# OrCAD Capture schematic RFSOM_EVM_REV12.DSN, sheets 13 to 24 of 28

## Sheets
13 09 RF_TX03: size A4
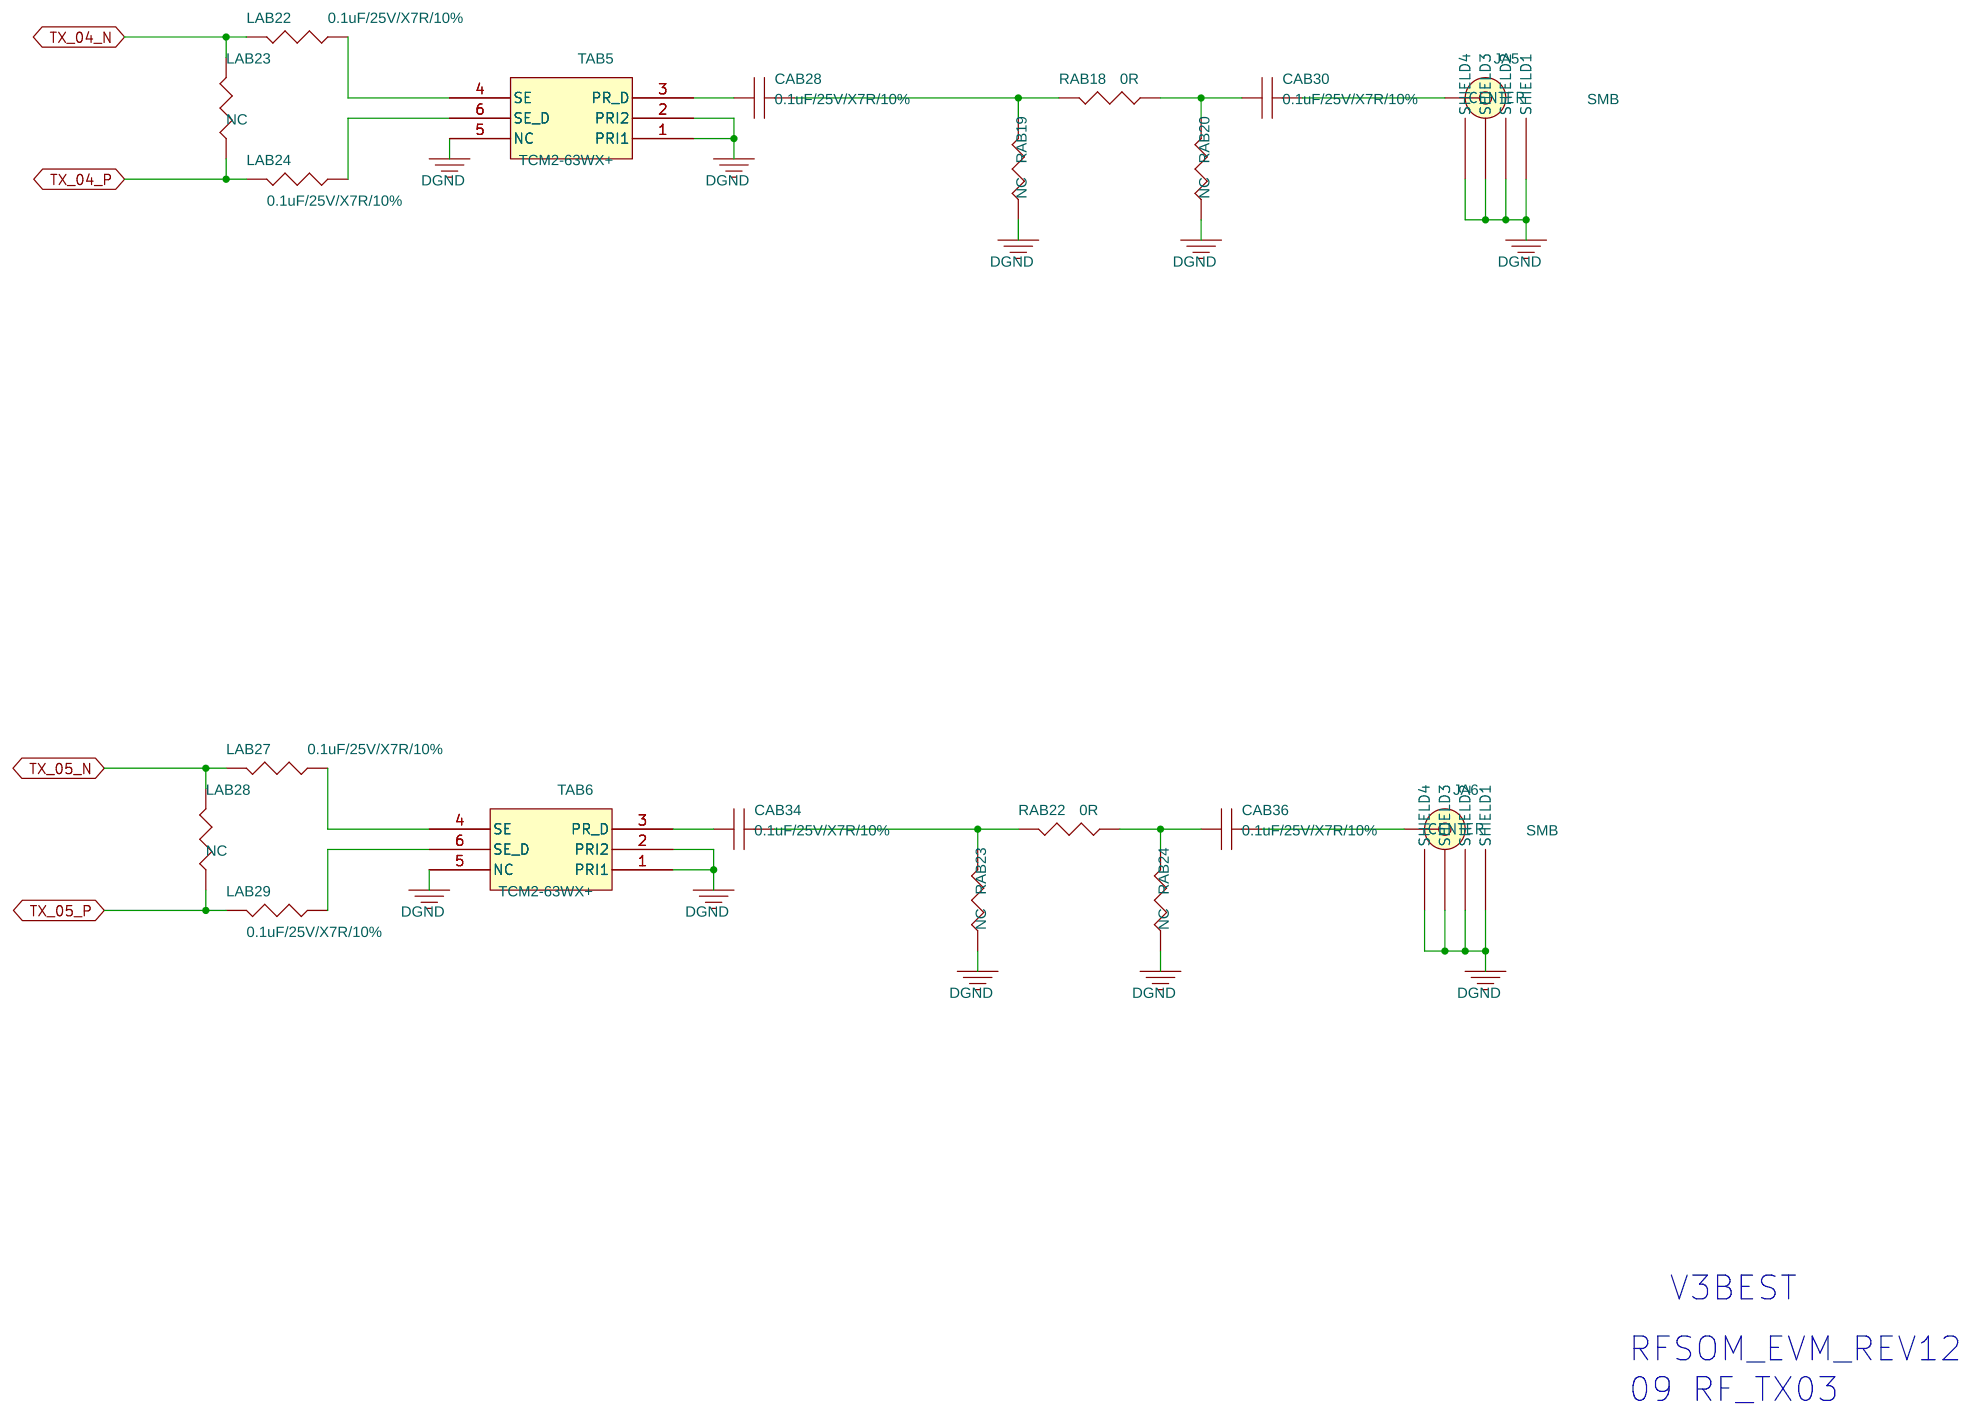
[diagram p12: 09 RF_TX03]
14 08 RF_TX02: size A4
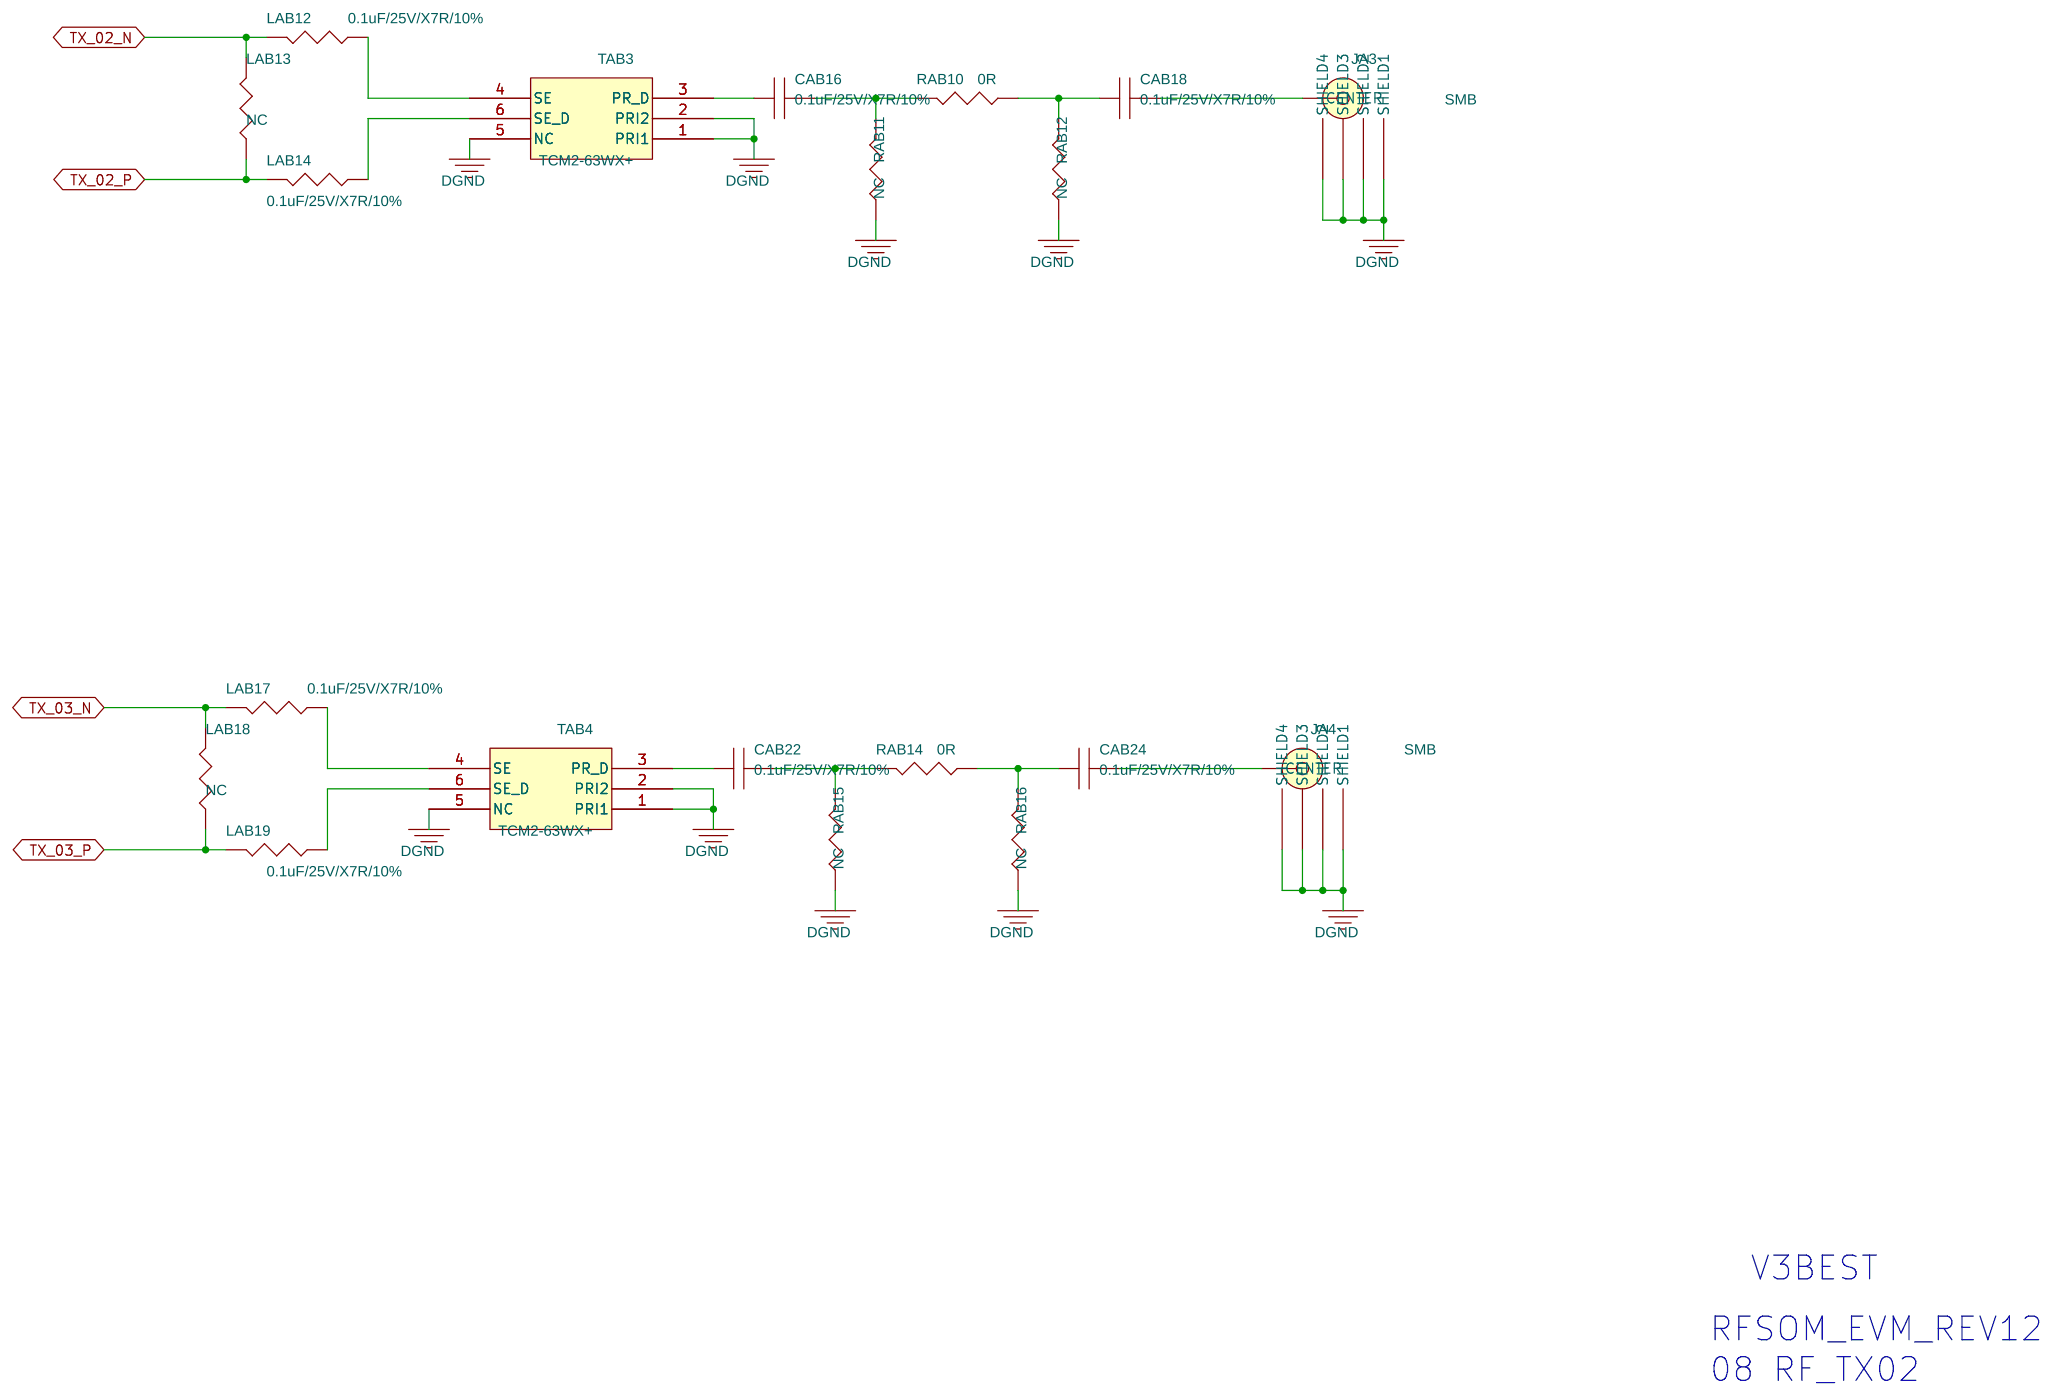
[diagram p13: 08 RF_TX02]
15 07 RF_TX01: size A4
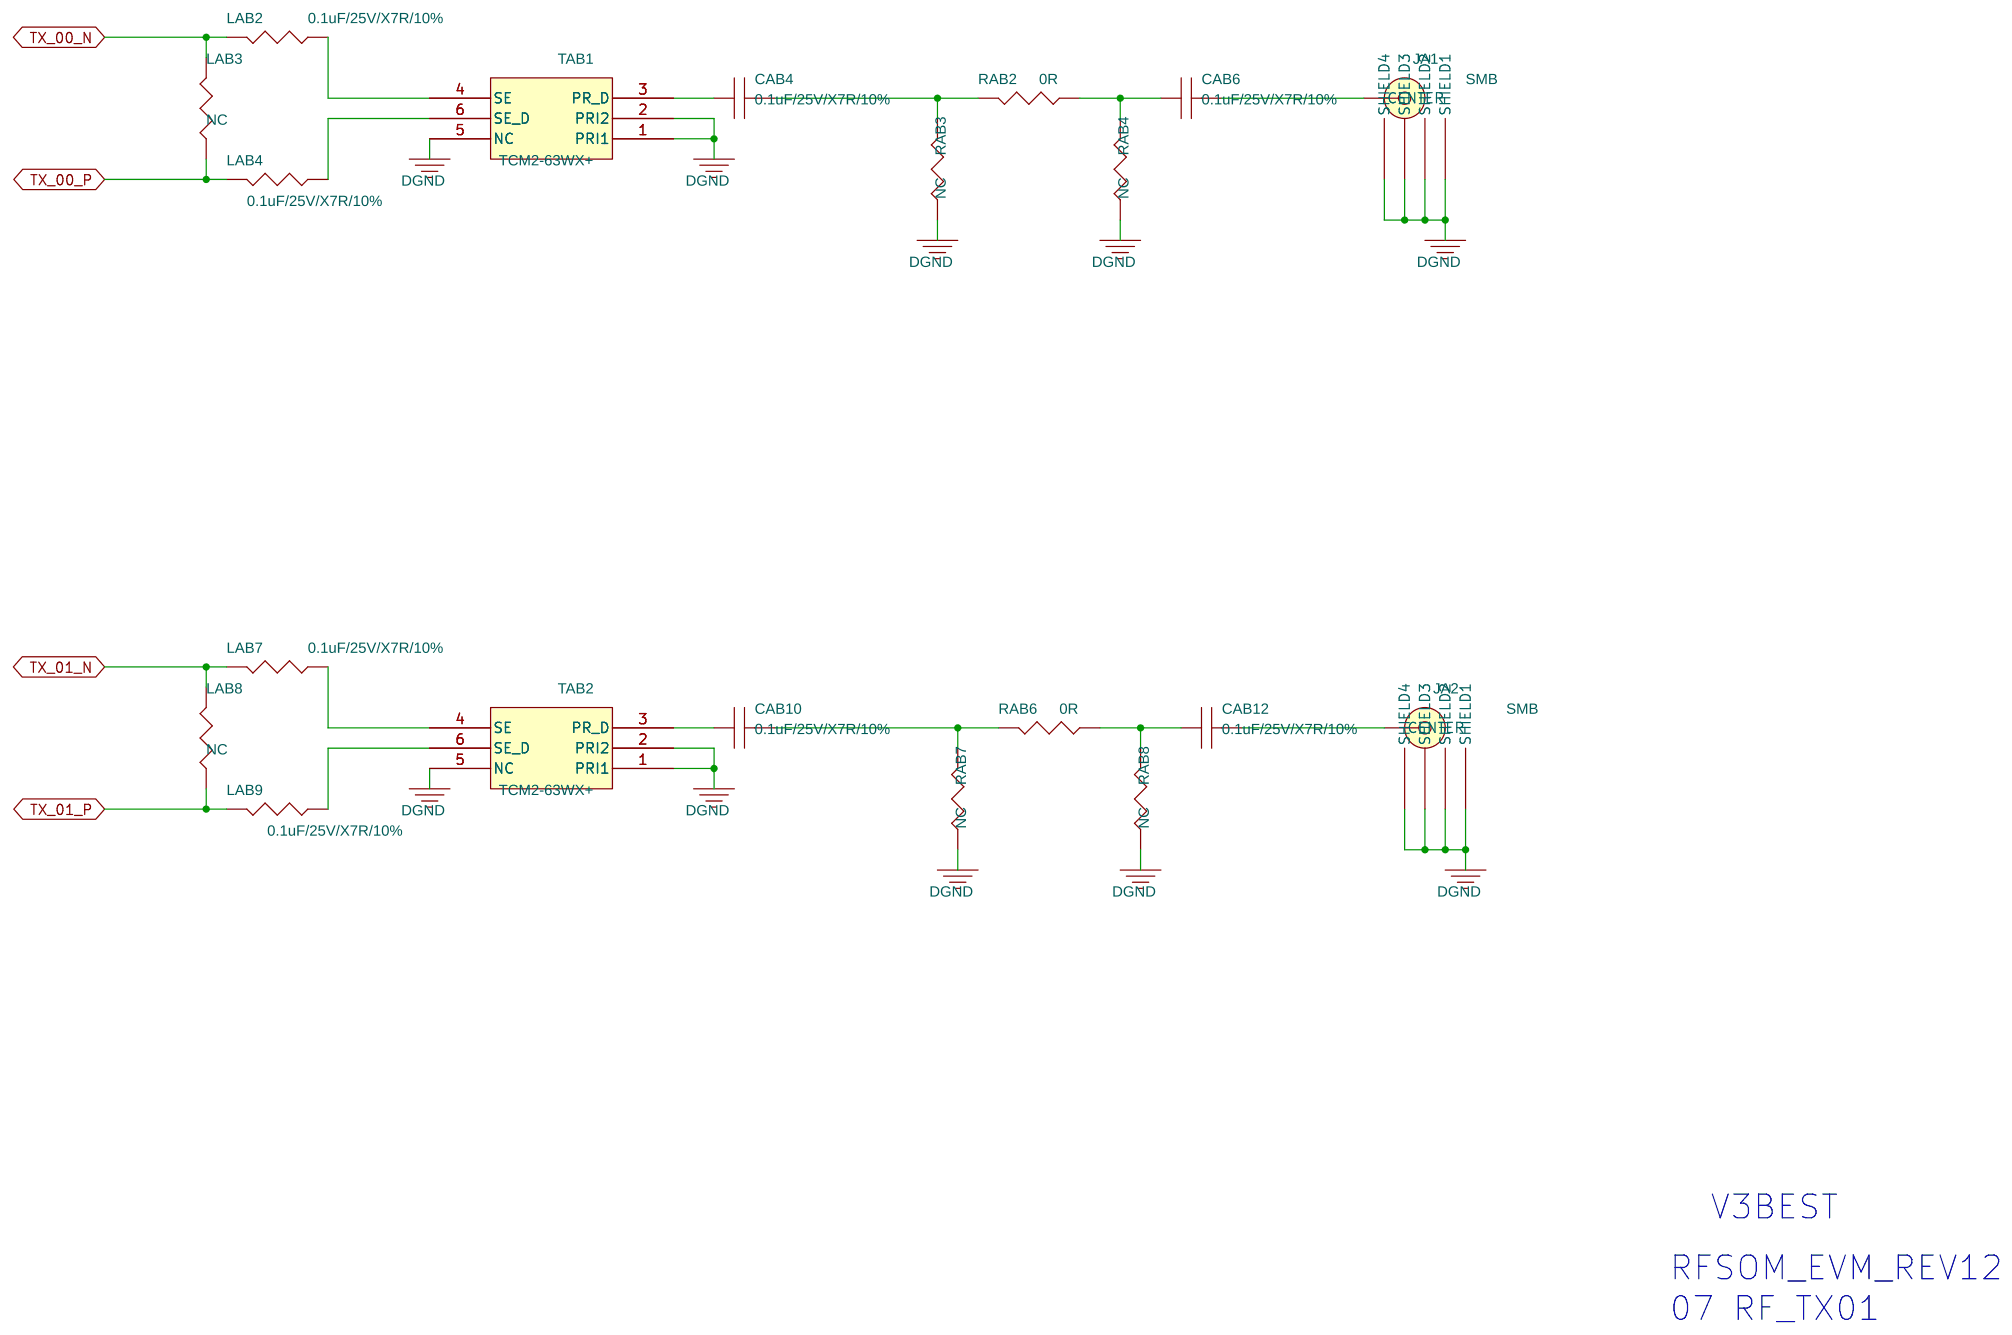
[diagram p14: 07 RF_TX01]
16 06 CORE_CONNECTOR03: size A4
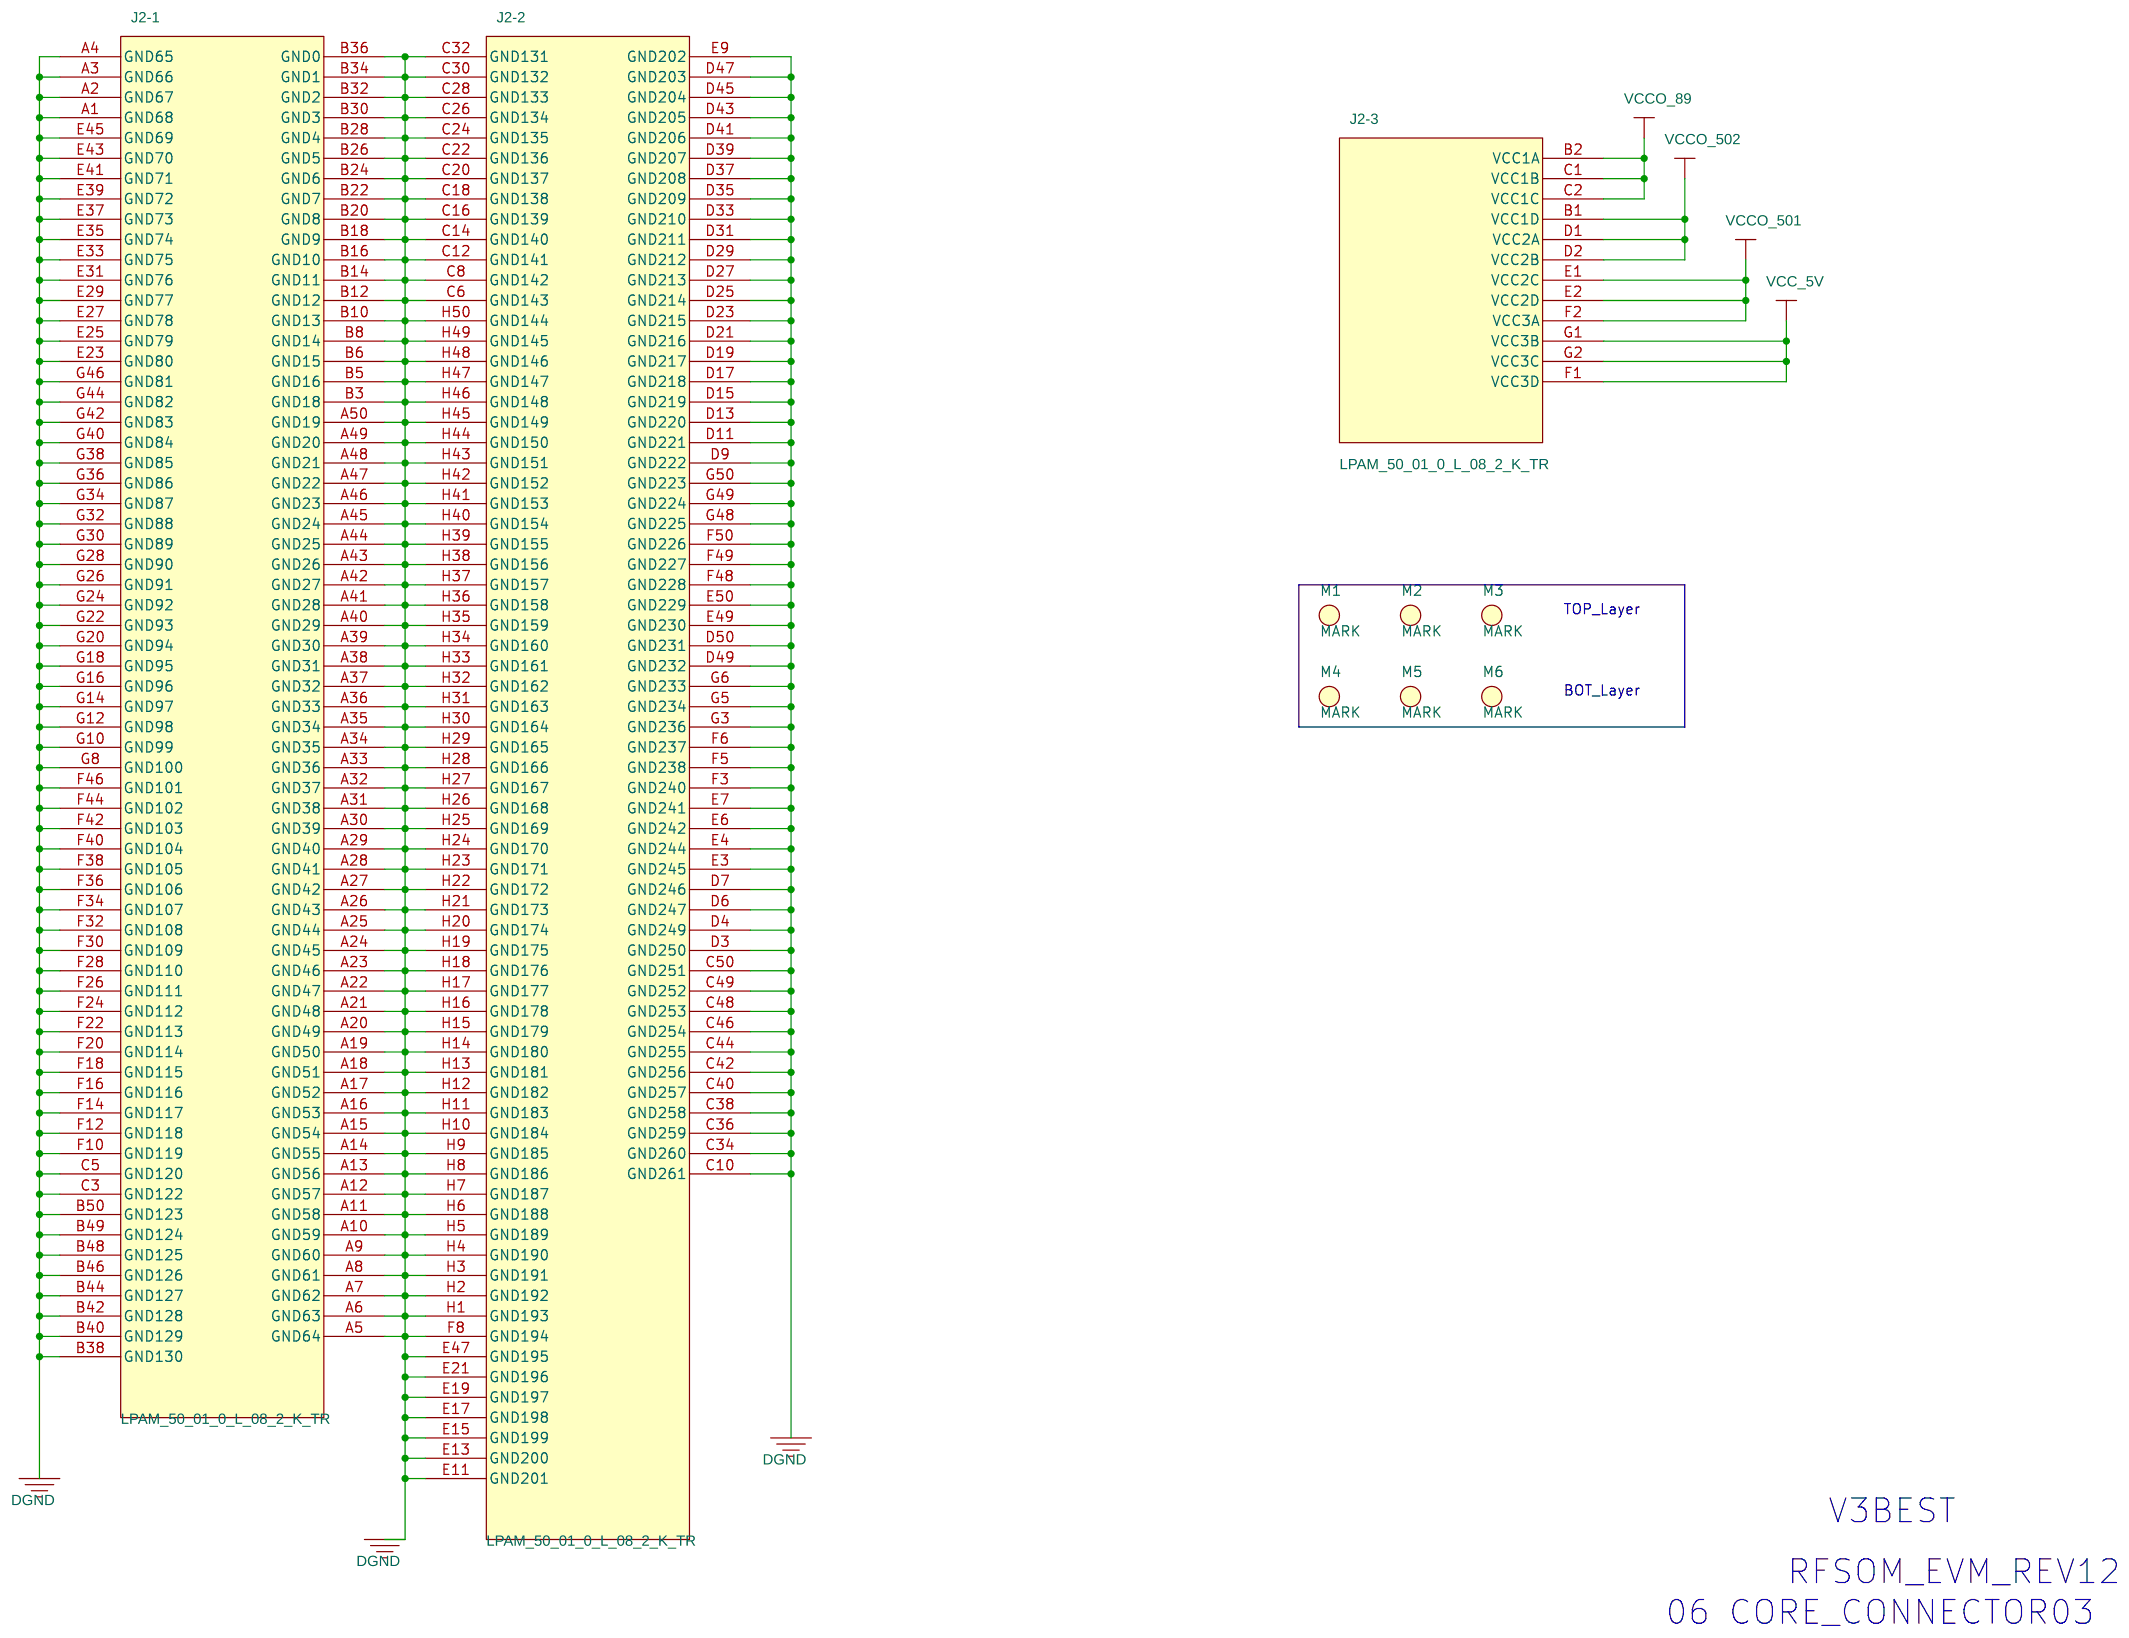
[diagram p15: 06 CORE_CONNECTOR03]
17 05 CORE_CONNECTOR02: size A4
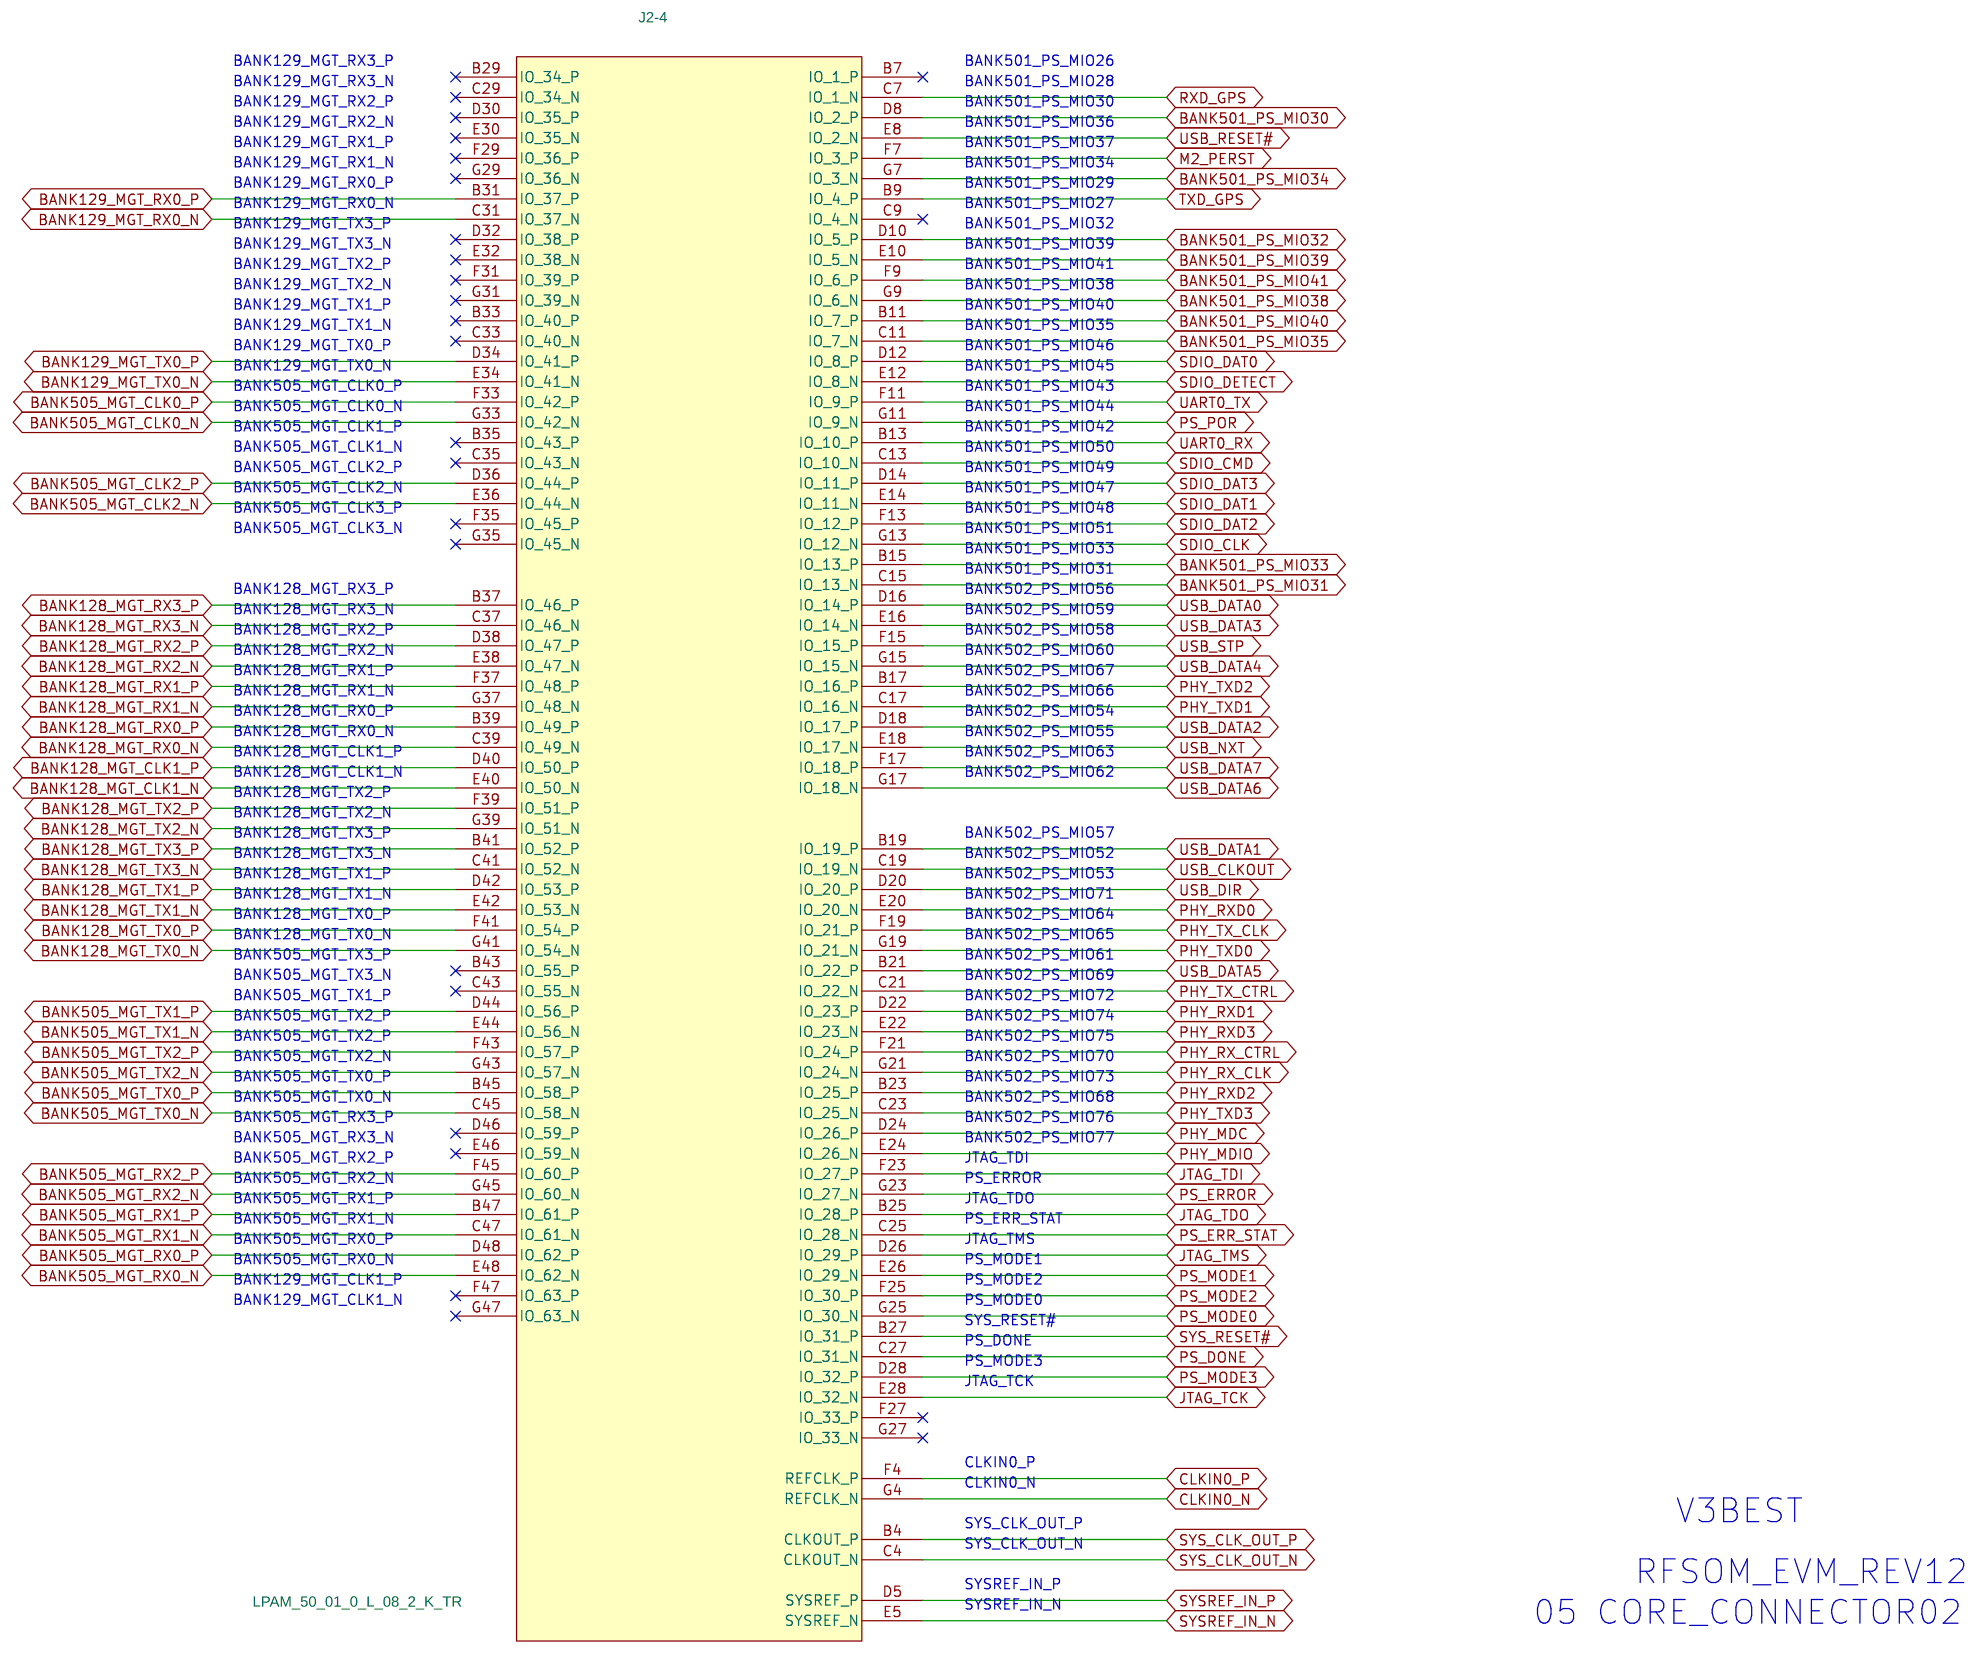
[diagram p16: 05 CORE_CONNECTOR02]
18 04 CORE_CONNECTOR01: size A4
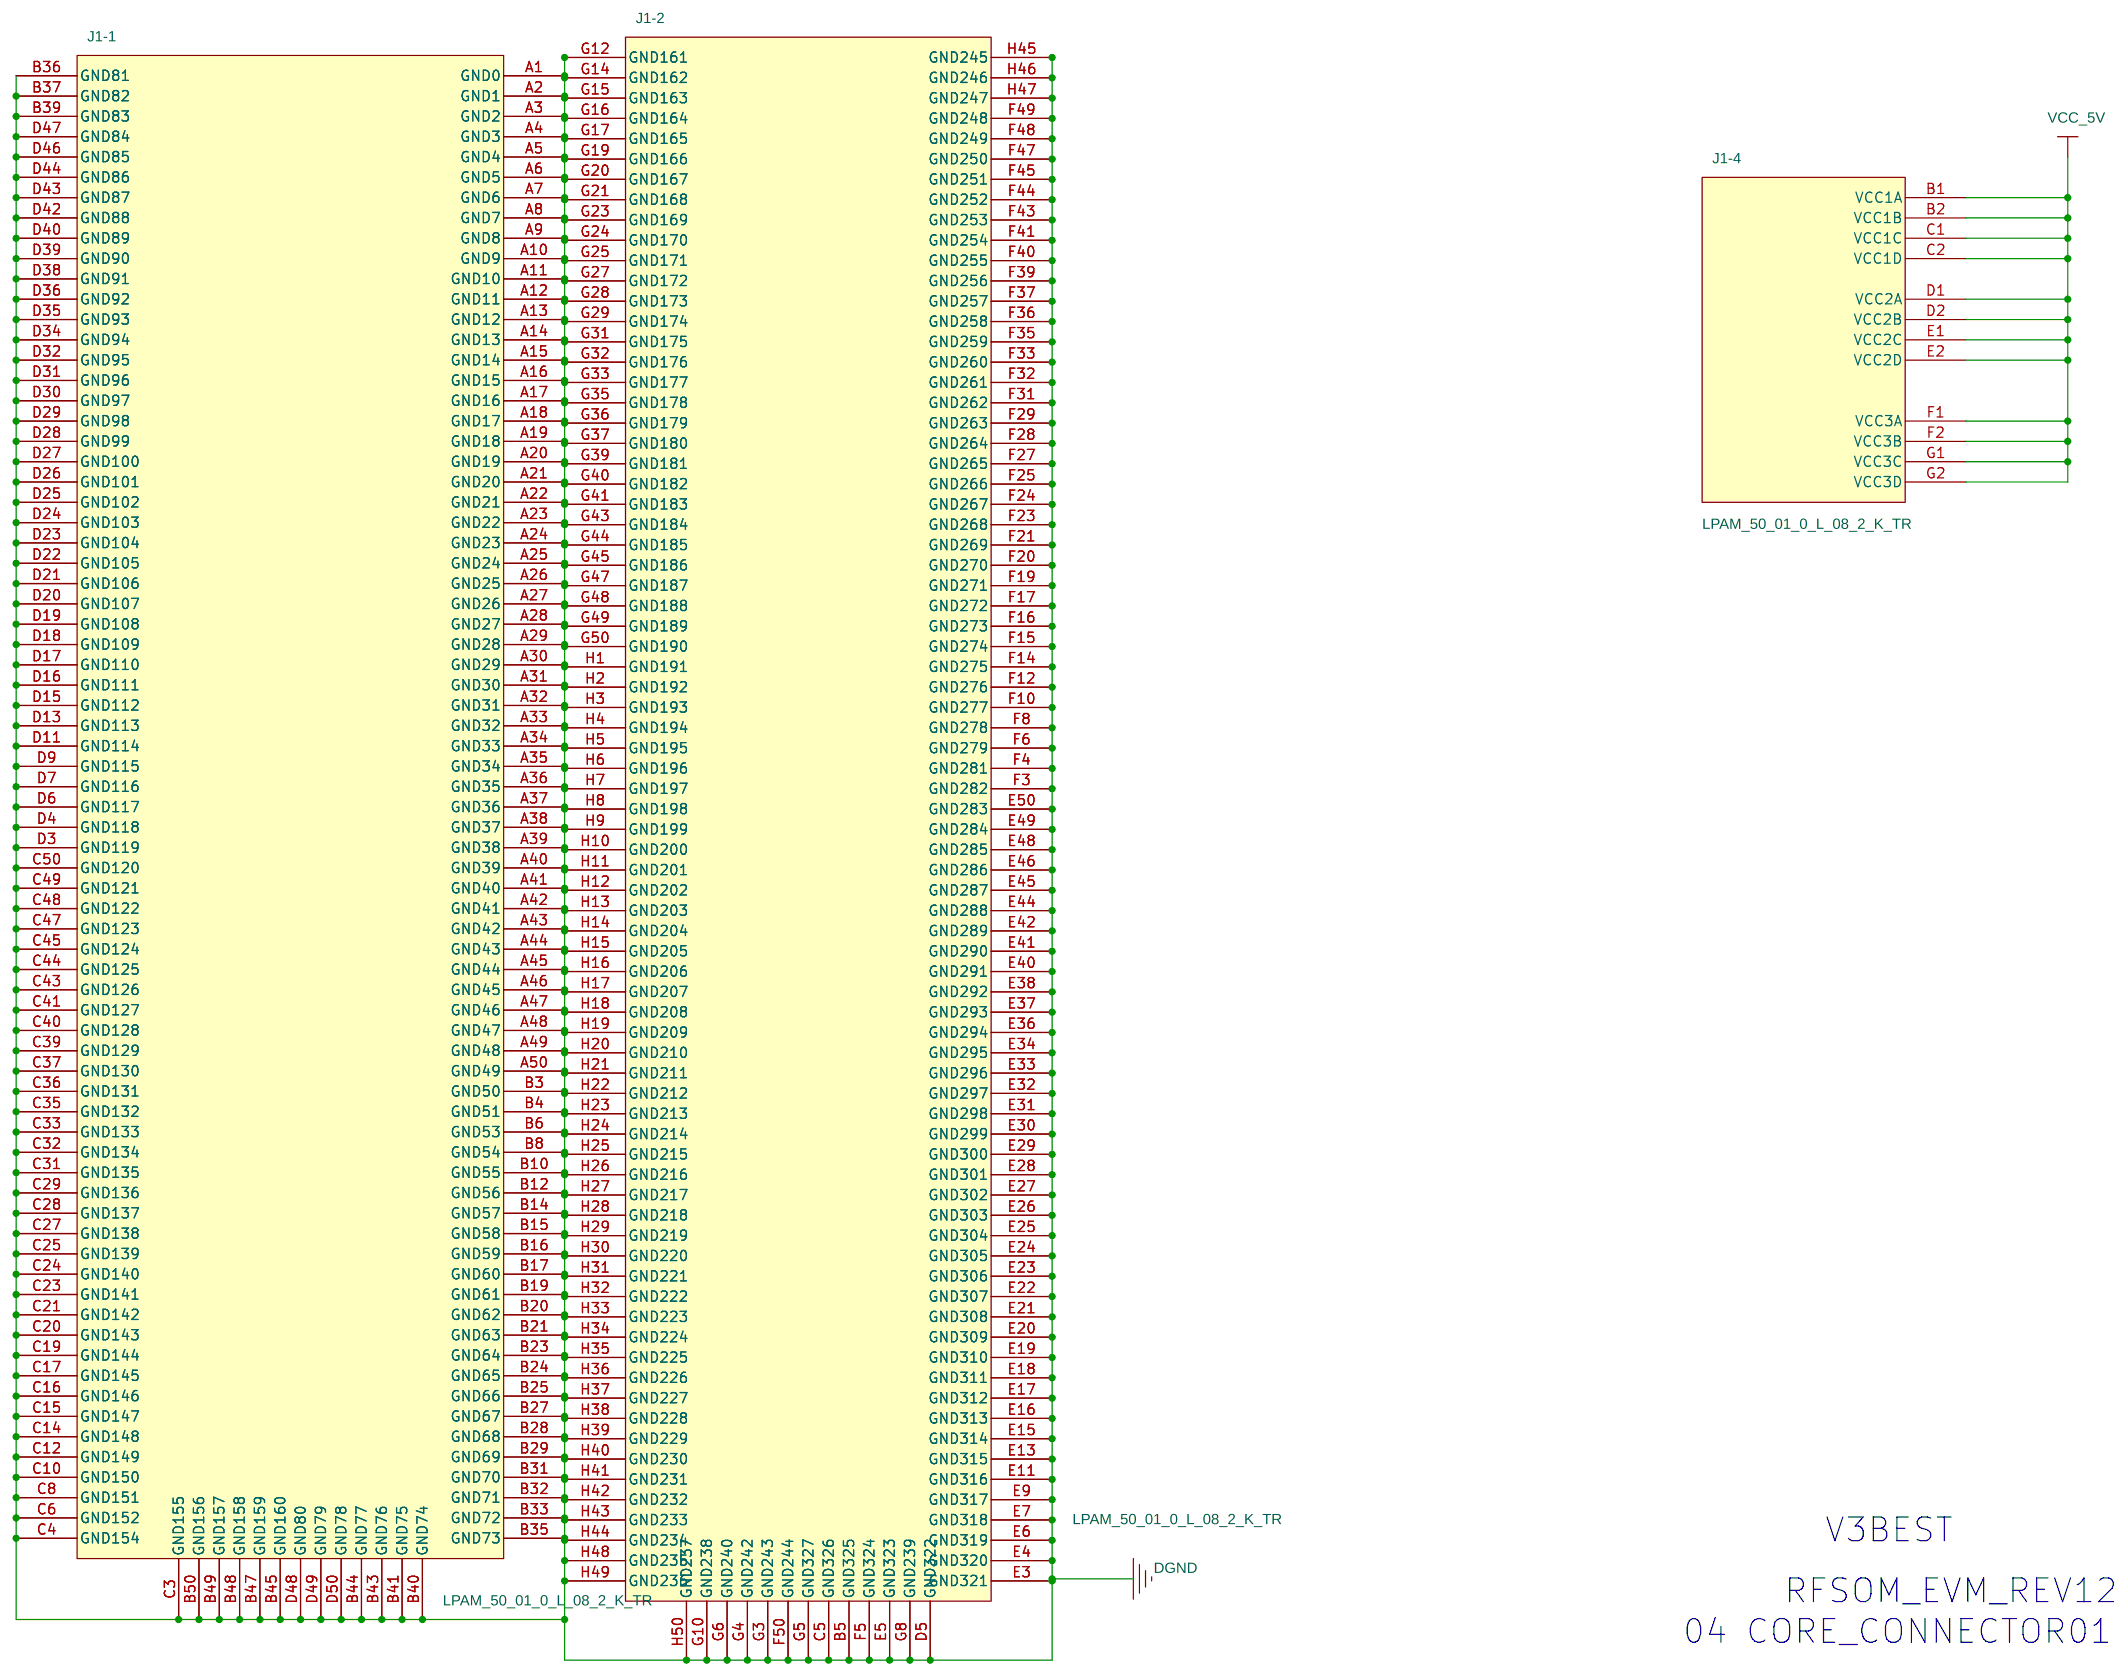
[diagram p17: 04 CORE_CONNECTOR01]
19 03 COER_CONNECTOR00: size A4
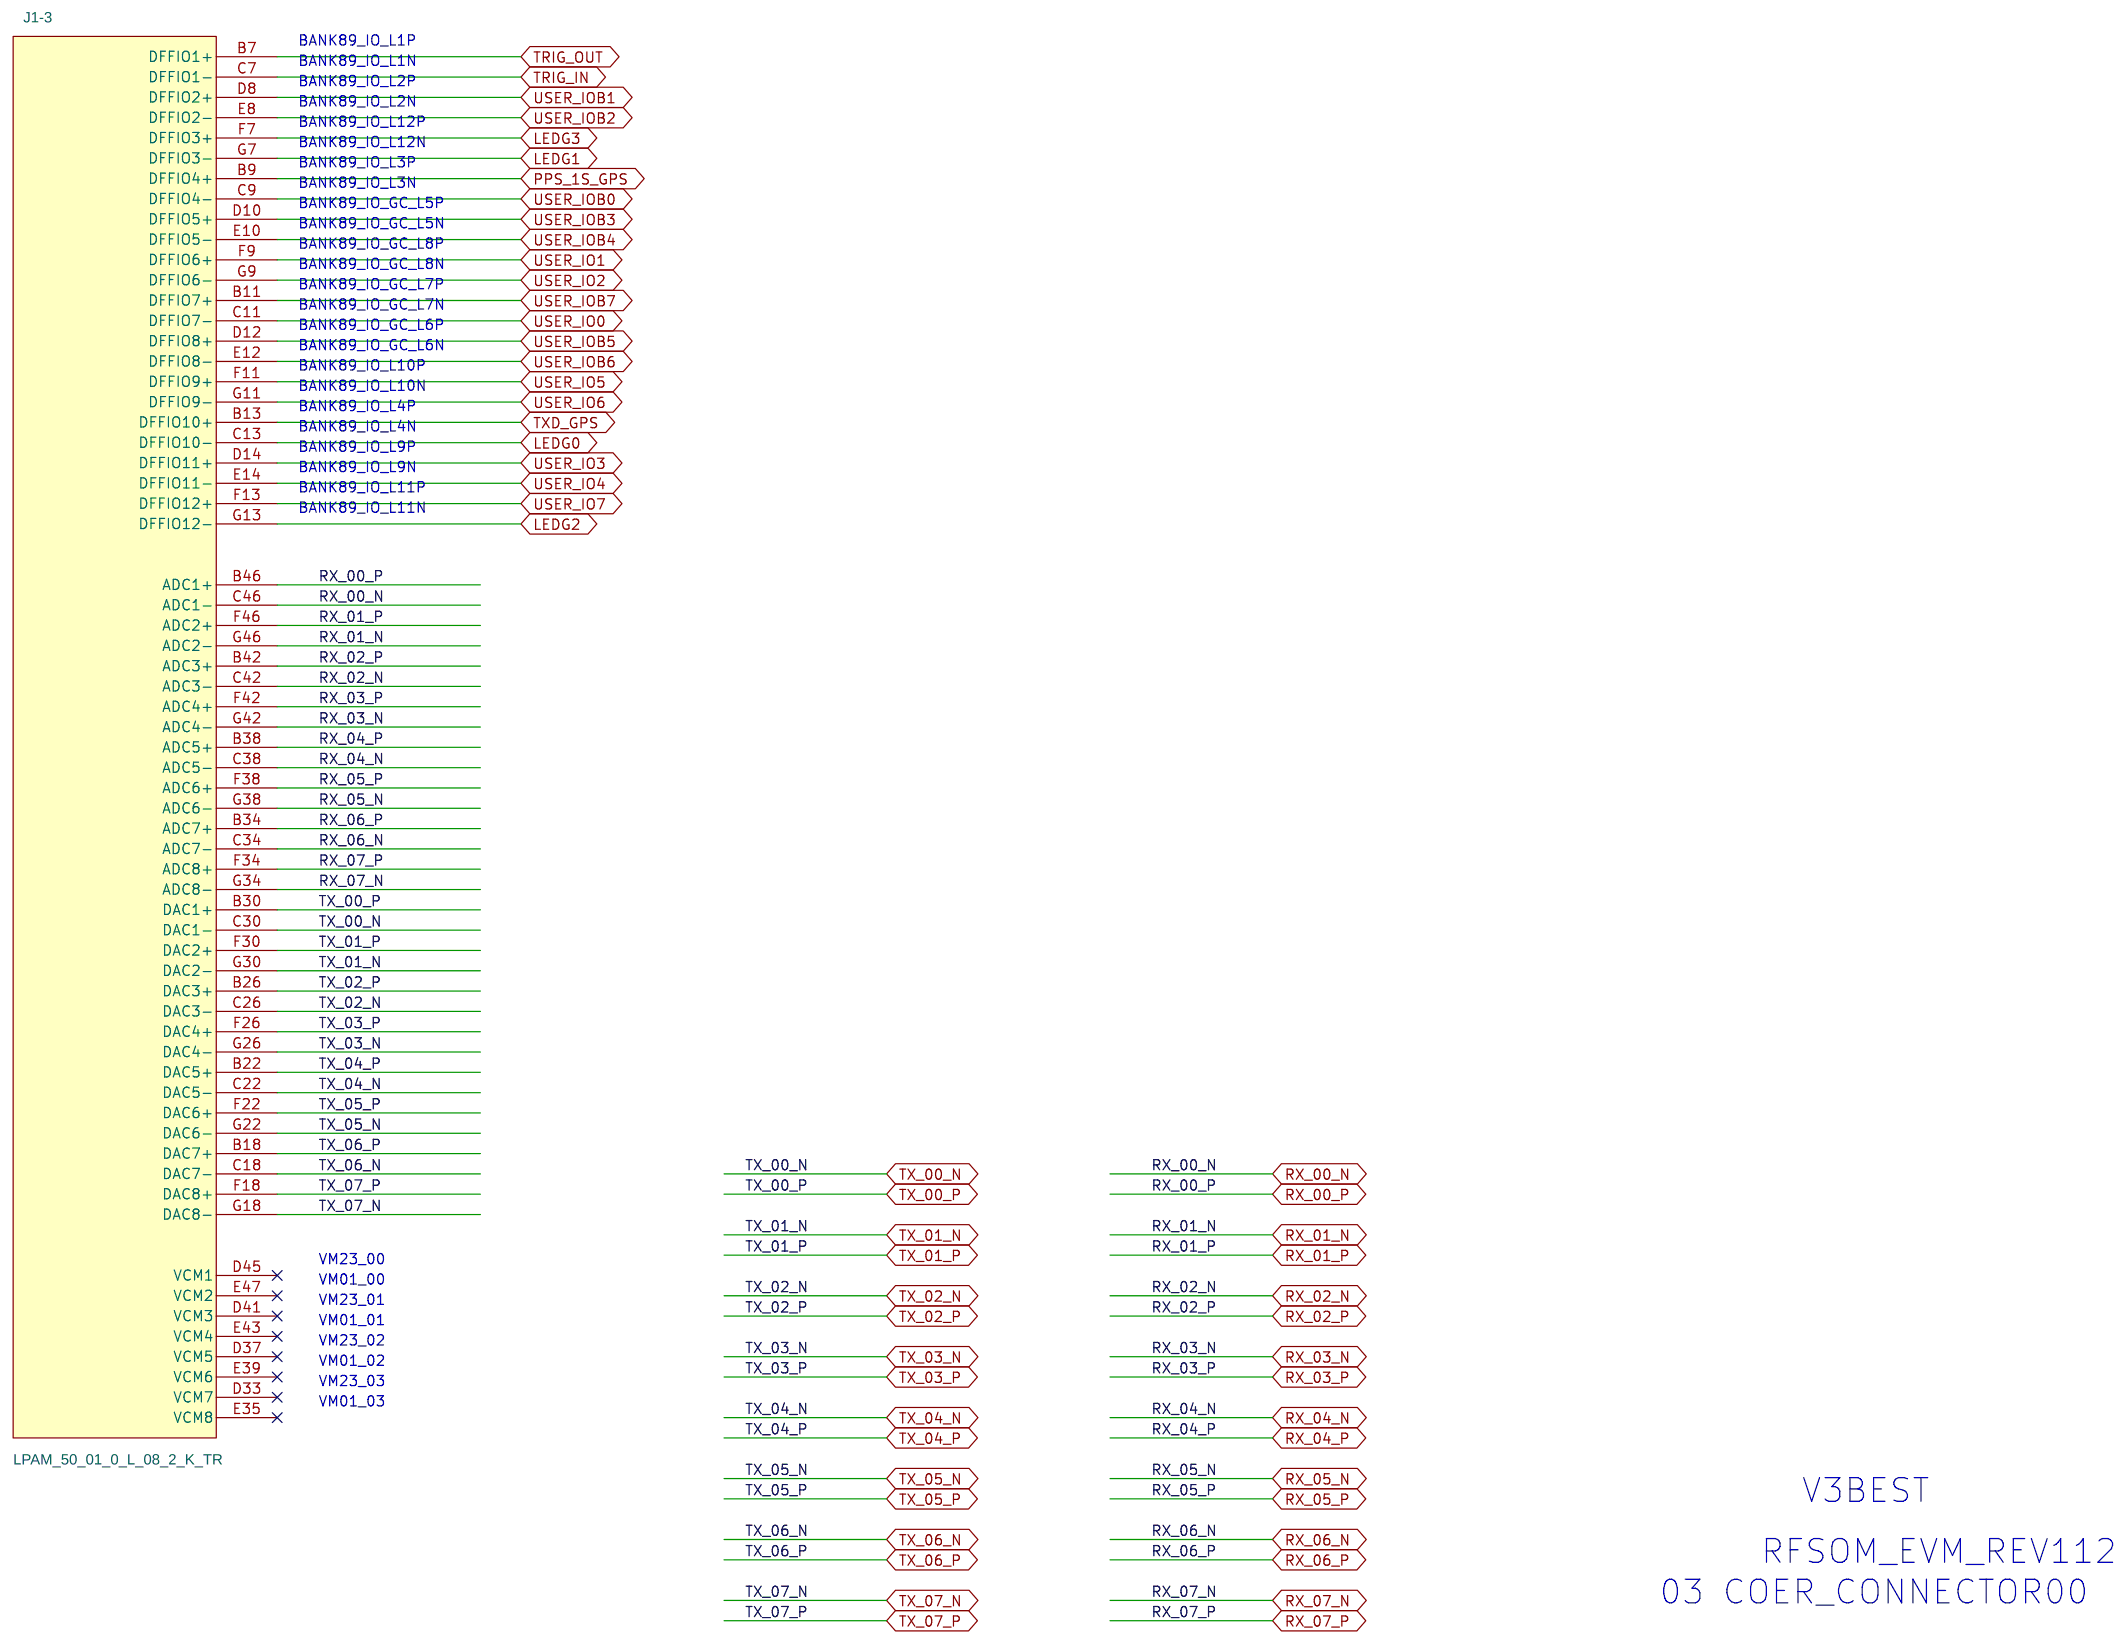
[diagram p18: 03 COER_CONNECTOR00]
20 23 USB3.0: size A4
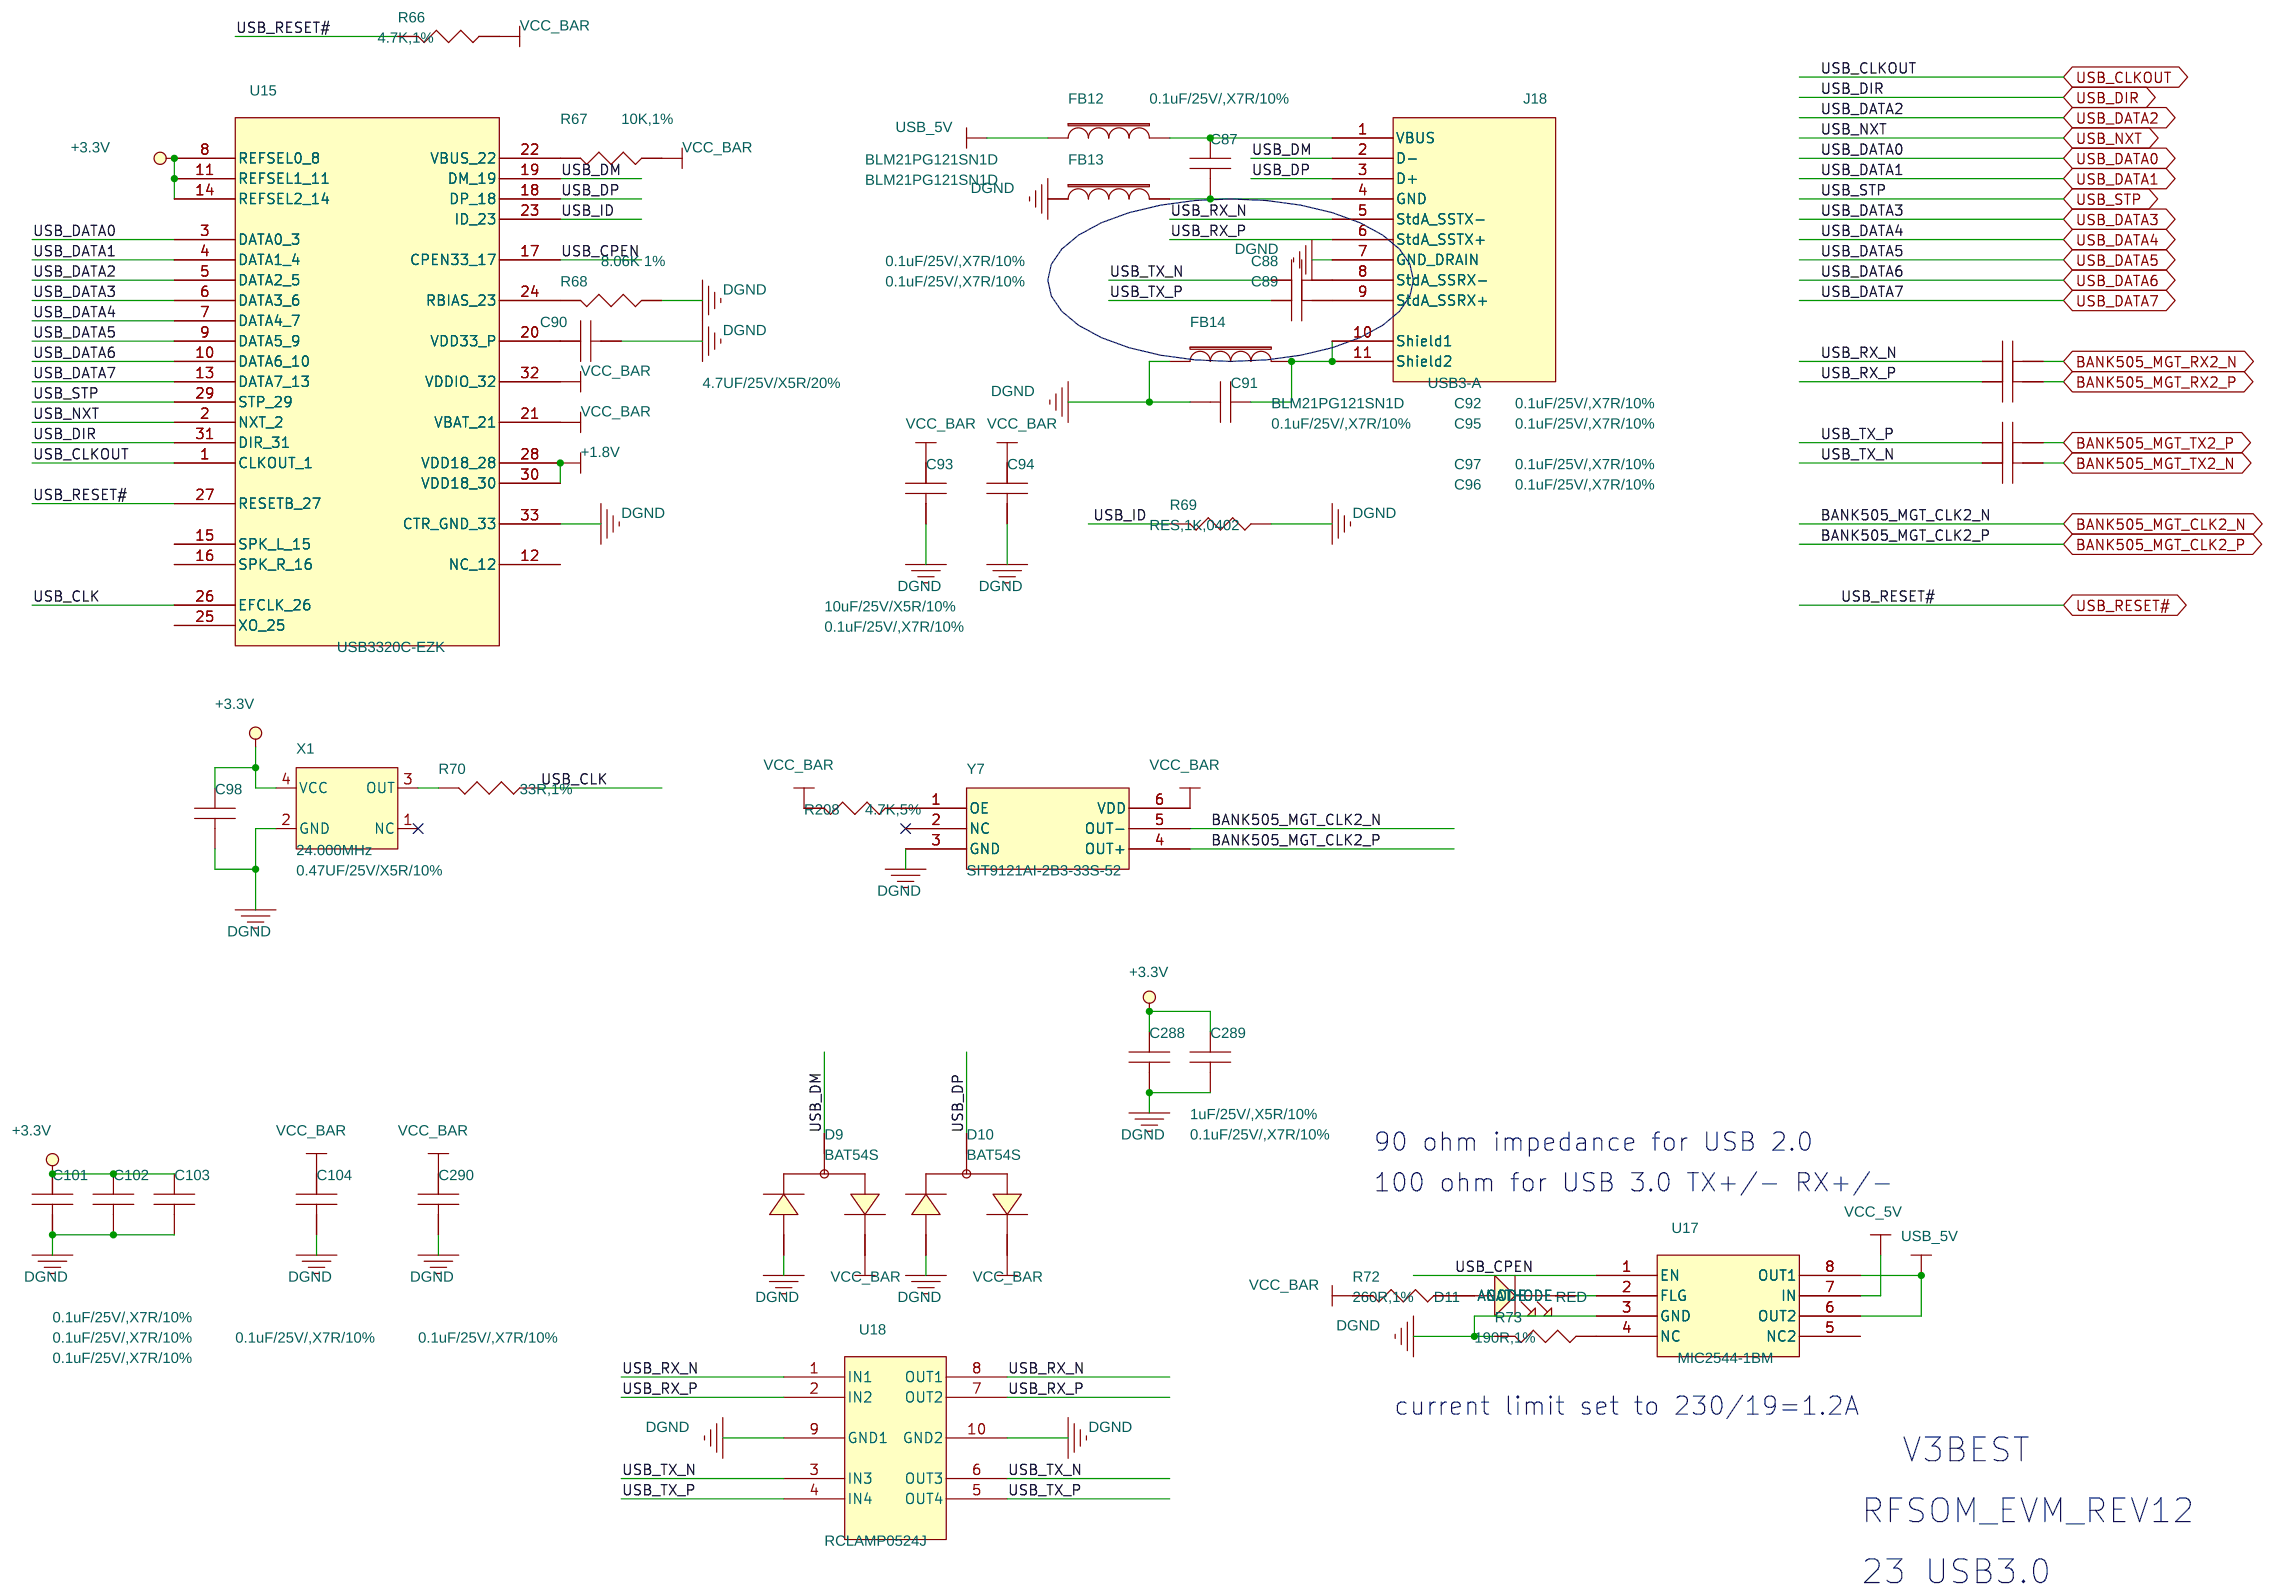
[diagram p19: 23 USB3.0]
21 22 NVME: size A4
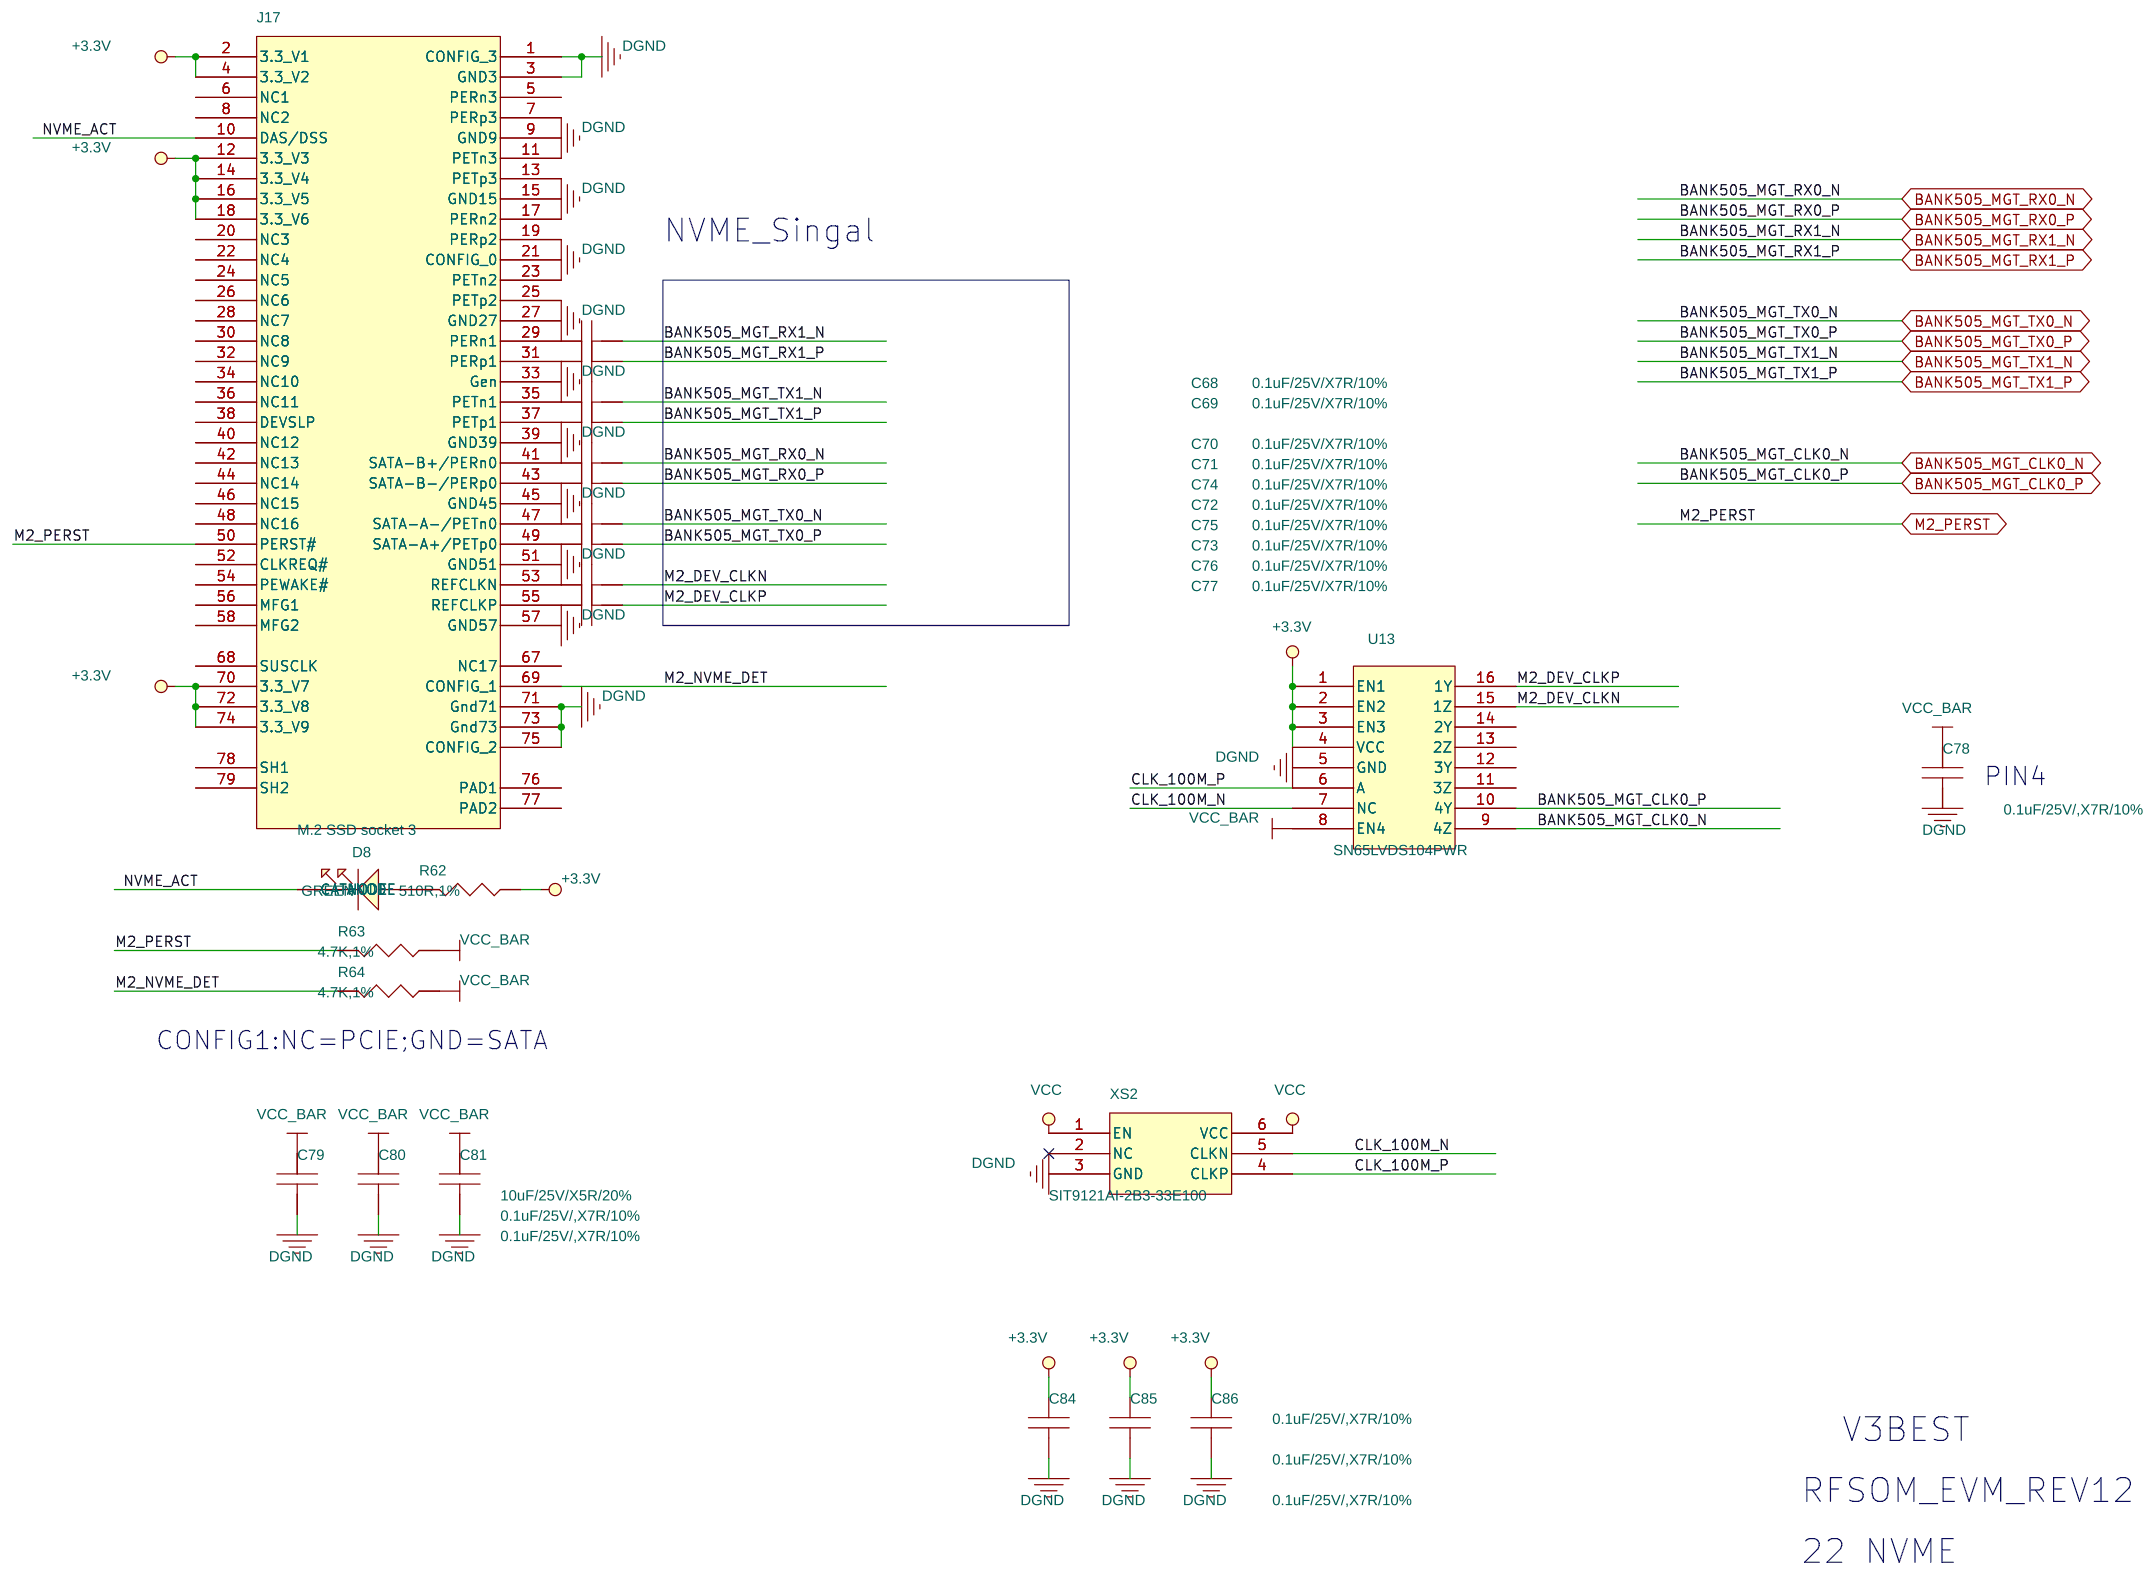
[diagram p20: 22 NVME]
22 00 PCB DESIGNER
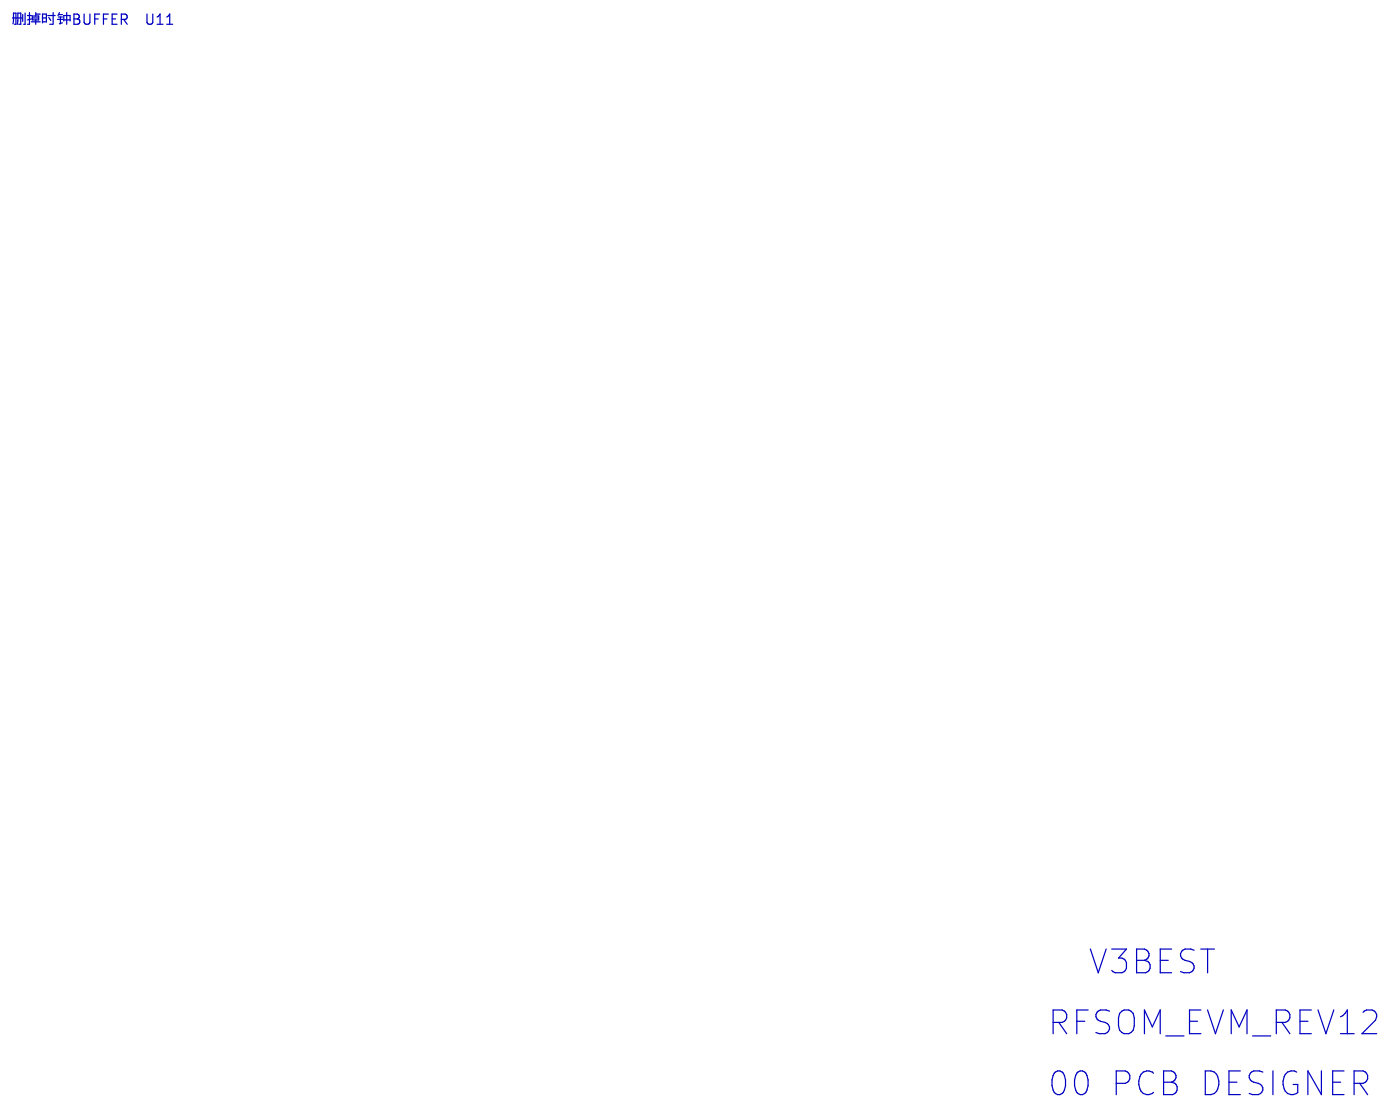
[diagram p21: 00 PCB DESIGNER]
23 15 FLASH: size A4
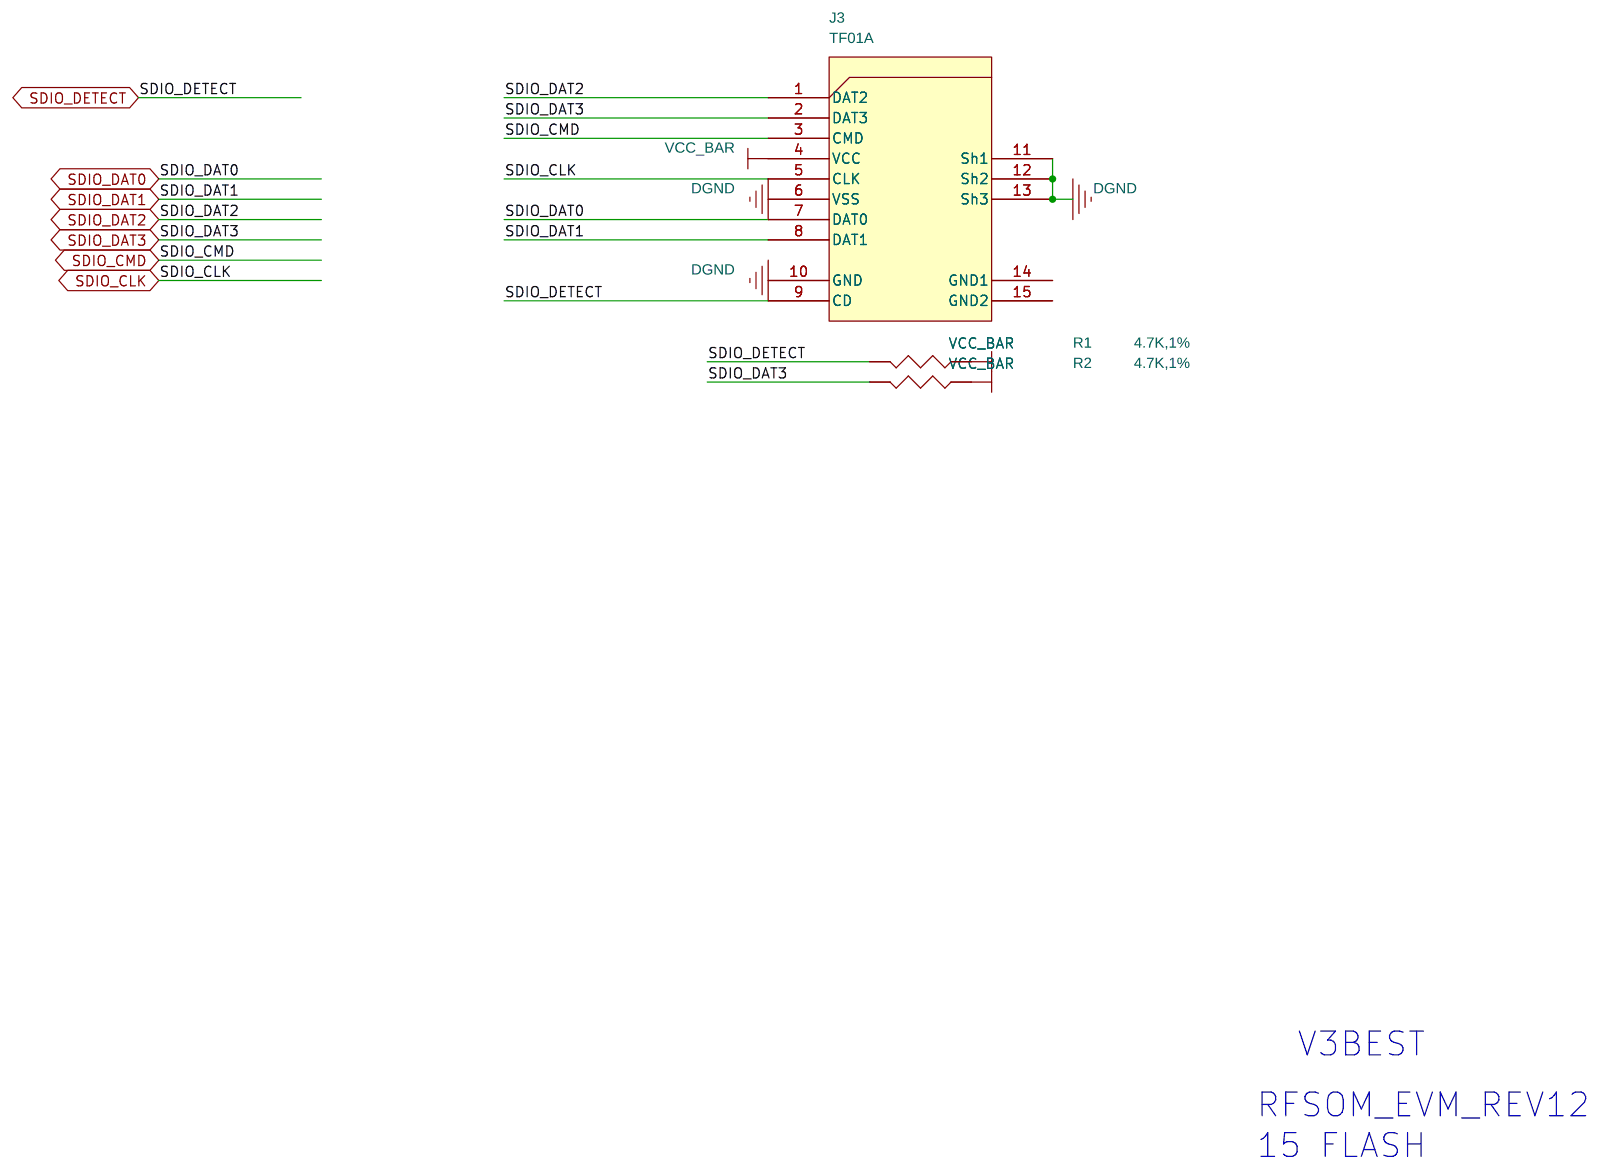
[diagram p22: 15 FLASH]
24 21 GPS: size A4
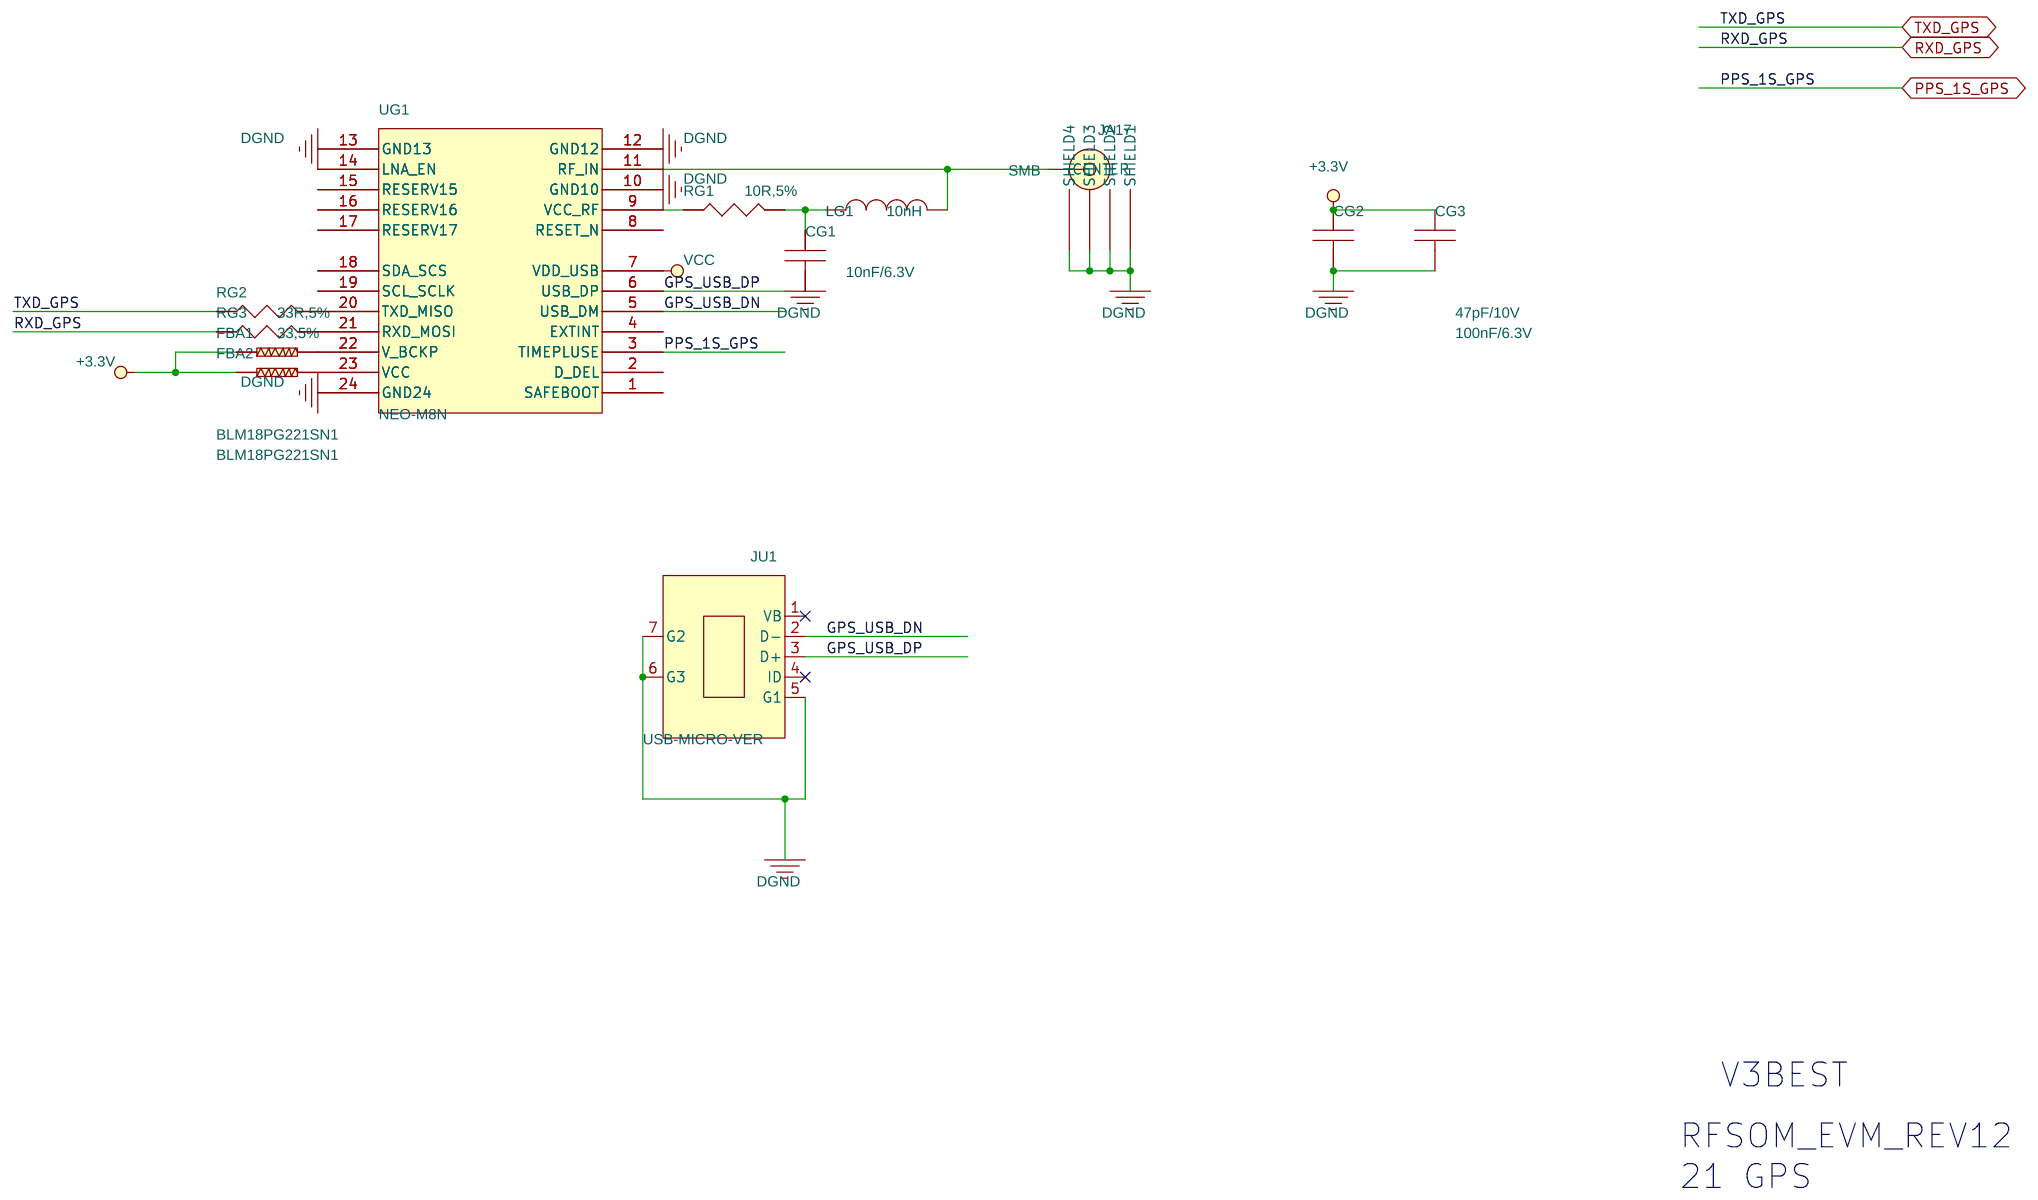
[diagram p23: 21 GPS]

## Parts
sheet 03 COER_CONNECTOR00
J1  LPAM_50_01_0_L_08_2_K_TR  [LPAM_50_01_TR]  (sections -1,-2,-3,-4)
sheet 05 CORE_CONNECTOR02
J2  LPAM_50_01_0_L_08_2_K_TR  [LPAM_50_01_TR]  (sections -1,-2,-3,-4)
sheet 06 CORE_CONNECTOR03
M1  MARK  [MARK]
M2  MARK  [MARK]
M3  MARK  [MARK]
M4  MARK  [MARK]
M5  MARK  [MARK]
M6  MARK  [MARK]
sheet 07 RF_TX01
CAB4  0.1uF/25V/X7R/10%  [0402C]
CAB6  0.1uF/25V/X7R/10%  [0402C]
CAB10  0.1uF/25V/X7R/10%  [0402C]
CAB12  0.1uF/25V/X7R/10%  [0402C]
JA1  SMB  [SMB_RF]
JA2  SMB  [SMB_RF]
LAB2  0.1uF/25V/X7R/10%  [0402C]
LAB3  NC  [0402C]
LAB4  0.1uF/25V/X7R/10%  [0402C]
LAB7  0.1uF/25V/X7R/10%  [0402C]
LAB8  NC  [0402C]
LAB9  0.1uF/25V/X7R/10%  [0402C]
RAB2  0R  [0402R]
RAB3  NC  [0402R]
RAB4  NC  [0402R]
RAB6  0R  [0402R]
RAB7  NC  [0402R]
RAB8  NC  [0402R]
TAB1  TCM2-63WX+  [tcm1-63ax_]
TAB2  TCM2-63WX+  [tcm1-63ax_]
sheet 08 RF_TX02
CAB16  0.1uF/25V/X7R/10%  [0402C]
CAB18  0.1uF/25V/X7R/10%  [0402C]
CAB22  0.1uF/25V/X7R/10%  [0402C]
CAB24  0.1uF/25V/X7R/10%  [0402C]
JA3  SMB  [SMB_RF]
JA4  SMB  [SMB_RF]
LAB12  0.1uF/25V/X7R/10%  [0402C]
LAB13  NC  [0402C]
LAB14  0.1uF/25V/X7R/10%  [0402C]
LAB17  0.1uF/25V/X7R/10%  [0402C]
LAB18  NC  [0402C]
LAB19  0.1uF/25V/X7R/10%  [0402C]
RAB10  0R  [0402R]
RAB11  NC  [0402R]
RAB12  NC  [0402R]
RAB14  0R  [0402R]
RAB15  NC  [0402R]
RAB16  NC  [0402R]
TAB3  TCM2-63WX+  [tcm1-63ax_]
TAB4  TCM2-63WX+  [tcm1-63ax_]
sheet 09 RF_TX03
CAB28  0.1uF/25V/X7R/10%  [0402C]
CAB30  0.1uF/25V/X7R/10%  [0402C]
CAB34  0.1uF/25V/X7R/10%  [0402C]
CAB36  0.1uF/25V/X7R/10%  [0402C]
JA5  SMB  [SMB_RF]
JA6  SMB  [SMB_RF]
LAB22  0.1uF/25V/X7R/10%  [0402C]
LAB23  NC  [0402C]
LAB24  0.1uF/25V/X7R/10%  [0402C]
LAB27  0.1uF/25V/X7R/10%  [0402C]
LAB28  NC  [0402C]
LAB29  0.1uF/25V/X7R/10%  [0402C]
RAB18  0R  [0402R]
RAB19  NC  [0402R]
RAB20  NC  [0402R]
RAB22  0R  [0402R]
RAB23  NC  [0402R]
RAB24  NC  [0402R]
TAB5  TCM2-63WX+  [tcm1-63ax_]
TAB6  TCM2-63WX+  [tcm1-63ax_]
sheet 15 FLASH
J3  TF01A  [TF01A]
R1  4.7K,1%  [R0402]
R2  4.7K,1%  [R0402]
sheet 21 GPS
CG1  10nF/6.3V  [0402C]
CG2  100nF/6.3V  [0402C]
CG3  47pF/10V  [0402C]
FBA1  BLM18PG221SN1  [0603L]
FBA2  BLM18PG221SN1  [0603L]
JA17  SMB  [SMB_RF]
JU1  USB-MICRO-VER  [USB-MICRO-VER]
LG1  10nH  [0603L]
RG1  10R,5%  [R0603]
RG2  33R,5%  [R0603]
RG3  33,5%  [R0603]
UG1  NEO-M8N  [NEO-M8N]
sheet 22 NVME
C68  0.1uF/25V/X7R/10%  [C0402]
C69  0.1uF/25V/X7R/10%  [C0402]
C70  0.1uF/25V/X7R/10%  [C0402]
C71  0.1uF/25V/X7R/10%  [C0402]
C72  0.1uF/25V/X7R/10%  [C0402]
C73  0.1uF/25V/X7R/10%  [C0402]
C74  0.1uF/25V/X7R/10%  [C0402]
C75  0.1uF/25V/X7R/10%  [C0402]
C76  0.1uF/25V/X7R/10%  [C0402]
C77  0.1uF/25V/X7R/10%  [C0402]
C78  0.1uF/25V/,X7R/10%  [C0402-BGA]
C79  10uF/25V/X5R/20%  [C1206]
C80  0.1uF/25V/,X7R/10%  [C0402-BGA]
C81  0.1uF/25V/,X7R/10%  [C0402-BGA]
C84  0.1uF/25V/,X7R/10%  [C1206]
C85  0.1uF/25V/,X7R/10%  [C0402-BGA]
C86  0.1uF/25V/,X7R/10%  [C0402-BGA]
D8  GREEN  [0603LED]
J17  M.2 SSD socket 3  [M2_2422]
R62  510R,1%  [R0402]
R63  4.7K,1%  [R0402]
R64  4.7K,1%  [R0402]
U13  SN65LVDS104PWR  [TSSOP16]
XS2  SIT9121AI-2B3-33E100  [XTALSMD_3225_DP]
sheet 23 USB3.0
C87  0.1uF/25V/,X7R/10%  [C0402-BGA]
C88  0.1uF/25V/,X7R/10%  [C0402]
C89  0.1uF/25V/,X7R/10%  [C0402]
C90  4.7UF/25V/X5R/20%  [C1206]
C91  0.1uF/25V/,X7R/10%  [C0402-BGA]
C92  0.1uF/25V/,X7R/10%  [C0402]
C93  10uF/25V/X5R/10%  [C1206]
C94  0.1uF/25V/,X7R/10%  [C0402-BGA]
C95  0.1uF/25V/,X7R/10%  [C0402]
C96  0.1uF/25V/,X7R/10%  [C0402]
C97  0.1uF/25V/,X7R/10%  [C0402]
C98  0.47UF/25V/X5R/10%  [C0402-BGA]
C101  0.1uF/25V/,X7R/10%  [C0402-BGA]
C102  0.1uF/25V/,X7R/10%  [C0402-BGA]
C103  0.1uF/25V/,X7R/10%  [C0402-BGA]
C104  0.1uF/25V/,X7R/10%  [C0402-BGA]
C288  1uF/25V/,X5R/10%  [C0402-BGA]
C289  0.1uF/25V/,X7R/10%  [C0402-BGA]
C290  0.1uF/25V/,X7R/10%  [C0402-BGA]
D9  BAT54S  [SO-G3]
D10  BAT54S  [SO-G3]
D11  RED  [0603LED]
FB12  BLM21PG121SN1D  [FB0805]
FB13  BLM21PG121SN1D  [FB0805]
FB14  BLM21PG121SN1D  [FB0805]
J18  USB3-A  [USB3-A]
R66  4.7K,1%  [R0402]
R67  10K,1%  [R0402]
R68  8.06K 1%  [R0402]
R69  RES,1K,0402  [R0402]
R70  33R,1%  [R0402]
R72  260R,1%  [R0402]
R73  190R,1%  [R0402]
R208  4.7K,5%  [R0402]
U15  USB3320C-EZK  [QFN32]
U17  MIC2544-1BM  [SO_8]
U18  RCLAMP0524J  [TVS_0524J]
X1  24.000MHz  [XTALSMD_3225]
Y7  SIT9121AI-2B3-33S-52  [XTALSMD_3225_DP]

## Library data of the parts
J1 = LPAF_50_03_L_08_2_TR_17
J2 = LPAM_50_01_L_08_7
M1-M6 = MARK
C68-C81 C84-C98 C101-C104 C288-C290 CAB4 CAB6 CAB10 CAB12 CAB16 CAB18 CAB22 CAB24 CAB28 CAB30 CAB34 CAB36 = CAP
JA1-JA6 JA17 = BNC_3
LAB2-LAB4 LAB7-LAB9 LAB12-LAB14 LAB17-LAB19 LAB22-LAB24 LAB27-LAB29 RAB2-RAB4 RAB6-RAB8 RAB10-RAB12 RAB14-RAB16 RAB18-RAB20 RAB22-RAB24 = RES
TAB1-TAB6 = TCM1_83X_P_1: REUSE_ANNOTATE: TRUE
J3 = mini_sd_1
R1 R2 R62-R64 R66-R70 R72 R73 R208 = RES-H
CG1-CG3 = CAP: REUSE_ANNOTATE: TRUE
FBA1 FBA2 = BLM18PG221SN1
JU1 = USB-MICRO-VAR
LG1 = INDUCTOR
RG1-RG3 = RES: REUSE_ANNOTATE: TRUE
UG1 = NEO-M8N
D8 D11 = LED
J17 = M_2_SLOT
U13 = SN65LVDS105
XS2 = SIT9121
D9 D10 = 40CPQ045_TO_0
FB12-FB14 = BLM21PG121SN1D
J18 = USB3-A
U15 = USB3320C-EZK
U17 = MIC2025-1BM
U18 = RCLAMP0524J
X1 = XTAL
Y7 = SIT9121AI-2D2-33E200.000000X

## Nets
+1.8V: R64.1 U15.28(VDD18) U15.30(VDD18) ; also on sheet 5 27
+3.3V: C78.1 C79.1 C80.1 C81.1 C84.1 C85.1 C86.1 C98.1 C101.1 C102.1 C103.1 C104.1 C288.1 C289.1 CG2.1 CG3.1 FBA1.2 FBA2.2 J3.4(VCC) J17.2(3.3_V1) J17.4(3.3_V2) J17.12(3.3_V3) J17.14(3.3_V4) J17.16(3.3_V5) J17.18(3.3_V6) J17.70(3.3_V7) J17.72(3.3_V8) J17.74(3.3_V9) R1.1 R2.1 R62.1 R63.1 R66.1 R72.2 R208.2 U13.1(EN1) U13.2(EN2) U13.3(EN3) U13.4(VCC) U13.8(EN4) U15.8(REFSEL0) U15.11(REFSEL1) U15.14(REFSEL2) U15.32(VDDIO) UG1.7(VDD_USB) X1.4(VCC) XS2.1(EN) XS2.6(VCC) Y7.6(VDD) ; also on sheet 2 3 4 5 7 25 27 28
DGND: C78.2 C79.2 C80.2 C81.2 C84.2 C85.2 C86.2 C90.2 C91.2 C93.2 C94.2 C98.2 C101.2 C102.2 C103.2 C104.2 C288.2 C289.2 C290.2 CG1.2 CG2.2 CG3.2 D9.1 D10.1 FB13.1 FB14.1 J1.A1(GND0) J1.A2(GND1) J1.A3(GND2) J1.A4(GND3) J1.A5(GND4) J1.A6(GND5) J1.A7(GND6) J1.A8(GND7) J1.A9(GND8) J1.A10(GND9) J1.A11(GND10) J1.A12(GND11) J1.A13(GND12) J1.A14(GND13) J1.A15(GND14) J1.A16(GND15) J1.A17(GND16) J1.A18(GND17) J1.A19(GND18) J1.A20(GND19) J1.A21(GND20) J1.A22(GND21) J1.A23(GND22) J1.A24(GND23) J1.A25(GND24) J1.A26(GND25) J1.A27(GND26) J1.A28(GND27) J1.A29(GND28) J1.A30(GND29) J1.A31(GND30) J1.A32(GND31) J1.A33(GND32) J1.A34(GND33) J1.A35(GND34) J1.A36(GND35) J1.A37(GND36) J1.A38(GND37) J1.A39(GND38) J1.A40(GND39) J1.A41(GND40) J1.A42(GND41) J1.A43(GND42) J1.A44(GND43) J1.A45(GND44) J1.A46(GND45) J1.A47(GND46) J1.A48(GND47) J1.A49(GND48) J1.A50(GND49) J1.B3(GND50) J1.B4(GND51) J1.B5(GND325) J1.B6(GND53) J1.B8(GND54) J1.B10(GND55) J1.B12(GND56) J1.B14(GND57) J1.B15(GND58) J1.B16(GND59) J1.B17(GND60) J1.B19(GND61) J1.B20(GND62) J1.B21(GND63) J1.B23(GND64) J1.B24(GND65) J1.B25(GND66) J1.B27(GND67) J1.B28(GND68) J1.B29(GND69) J1.B31(GND70) J1.B32(GND71) J1.B33(GND72) J1.B35(GND73) J1.B36(GND81) J1.B37(GND82) J1.B39(GND83) J1.B40(GND74) J1.B41(GND75) J1.B43(GND76) J1.B44(GND77) J1.B45(GND160) J1.B47(GND159) J1.B48(GND158) J1.B49(GND157) J1.B50(GND156) J1.C3(GND155) J1.C4(GND154) J1.C5(GND326) J1.C6(GND152) J1.C8(GND151) J1.C10(GND150) J1.C12(GND149) J1.C14(GND148) J1.C15(GND147) J1.C16(GND146) J1.C17(GND145) J1.C19(GND144) J1.C20(GND143) J1.C21(GND142) J1.C23(GND141) J1.C24(GND140) J1.C25(GND139) J1.C27(GND138) J1.C28(GND137) J1.C29(GND136) J1.C31(GND135) J1.C32(GND134) J1.C33(GND133) J1.C35(GND132) J1.C36(GND131) J1.C37(GND130) J1.C39(GND129) J1.C40(GND128) J1.C41(GND127) J1.C43(GND126) J1.C44(GND125) J1.C45(GND124) J1.C47(GND123) J1.C48(GND122) J1.C49(GND121) J1.C50(GND120) J1.D3(GND119) J1.D4(GND118) J1.D5(GND322) J1.D6(GND117) J1.D7(GND116) J1.D9(GND115) J1.D11(GND114) J1.D13(GND113) J1.D15(GND112) J1.D16(GND111) J1.D17(GND110) J1.D18(GND109) J1.D19(GND108) J1.D20(GND107) J1.D21(GND106) J1.D22(GND105) J1.D23(GND104) J1.D24(GND103) J1.D25(GND102) J1.D26(GND101) J1.D27(GND100) J1.D28(GND99) J1.D29(GND98) J1.D30(GND97) J1.D31(GND96) J1.D32(GND95) J1.D34(GND94) J1.D35(GND93) J1.D36(GND92) J1.D38(GND91) J1.D39(GND90) J1.D40(GND89) J1.D42(GND88) J1.D43(GND87) J1.D44(GND86) J1.D46(GND85) J1.D47(GND84) J1.D48(GND80) J1.D49(GND79) J1.D50(GND78) J1.E3(GND321) J1.E4(GND320) J1.E5(GND323) J1.E6(GND319) J1.E7(GND318) J1.E9(GND317) J1.E11(GND316) J1.E13(GND315) J1.E15(GND314) J1.E16(GND313) J1.E17(GND312) J1.E18(GND311) J1.E19(GND310) J1.E20(GND309) J1.E21(GND308) J1.E22(GND307) J1.E23(GND306) J1.E24(GND305) J1.E25(GND304) J1.E26(GND303) J1.E27(GND302) J1.E28(GND301) J1.E29(GND300) J1.E30(GND299) J1.E31(GND298) J1.E32(GND297) J1.E33(GND296) J1.E34(GND295) J1.E36(GND294) J1.E37(GND293) J1.E38(GND292) J1.E40(GND291) J1.E41(GND290) J1.E42(GND289) J1.E44(GND288) J1.E45(GND287) J1.E46(GND286) J1.E48(GND285) J1.E49(GND284) J1.E50(GND283) J1.F3(GND282) J1.F4(GND281) J1.F5(GND324) J1.F6(GND279) J1.F8(GND278) J1.F10(GND277) J1.F12(GND276) J1.F14(GND275) J1.F15(GND274) J1.F16(GND273) J1.F17(GND272) J1.F19(GND271) J1.F20(GND270) J1.F21(GND269) J1.F23(GND268) J1.F24(GND267) J1.F25(GND266) J1.F27(GND265) J1.F28(GND264) J1.F29(GND263) J1.F31(GND262) J1.F32(GND261) J1.F33(GND260) J1.F35(GND259) J1.F36(GND258) J1.F37(GND257) J1.F39(GND256) J1.F40(GND255) J1.F41(GND254) J1.F43(GND253) J1.F44(GND252) J1.F45(GND251) J1.F47(GND250) J1.F48(GND249) J1.F49(GND248) J1.F50(GND244) J1.G3(GND243) J1.G4(GND242) J1.G5(GND327) J1.G6(GND240) J1.G8(GND239) J1.G10(GND238) J1.G12(GND161) J1.G14(GND162) J1.G15(GND163) J1.G16(GND164) J1.G17(GND165) J1.G19(GND166) J1.G20(GND167) J1.G21(GND168) J1.G23(GND169) J1.G24(GND170) J1.G25(GND171) J1.G27(GND172) J1.G28(GND173) J1.G29(GND174) J1.G31(GND175) J1.G32(GND176) J1.G33(GND177) J1.G35(GND178) J1.G36(GND179) J1.G37(GND180) J1.G39(GND181) J1.G40(GND182) J1.G41(GND183) J1.G43(GND184) J1.G44(GND185) J1.G45(GND186) J1.G47(GND187) J1.G48(GND188) J1.G49(GND189) J1.G50(GND190) J1.H1(GND191) J1.H2(GND192) J1.H3(GND193) J1.H4(GND194) J1.H5(GND195) J1.H6(GND196) J1.H7(GND197) J1.H8(GND198) J1.H9(GND199) J1.H10(GND200) J1.H11(GND201) J1.H12(GND202) J1.H13(GND203) J1.H14(GND204) J1.H15(GND205) J1.H16(GND206) J1.H17(GND207) J1.H18(GND208) J1.H19(GND209) J1.H20(GND210) J1.H21(GND211) J1.H22(GND212) J1.H23(GND213) J1.H24(GND214) J1.H25(GND215) J1.H26(GND216) J1.H27(GND217) J1.H28(GND218) J1.H29(GND219) J1.H30(GND220) J1.H31(GND221) J1.H32(GND222) J1.H33(GND223) J1.H34(GND224) J1.H35(GND225) J1.H36(GND226) J1.H37(GND227) J1.H38(GND228) J1.H39(GND229) J1.H40(GND230) J1.H41(GND231) J1.H42(GND232) J1.H43(GND233) J1.H44(GND234) J1.H45(GND245) J1.H46(GND246) J1.H47(GND247) J1.H48(GND235) J1.H49(GND236) J1.H50(GND237) J2.A1(GND68) J2.A2(GND67) J2.A3(GND66) J2.A4(GND65) J2.A5(GND64) J2.A6(GND63) J2.A7(GND62) J2.A8(GND61) J2.A9(GND60) J2.A10(GND59) J2.A11(GND58) J2.A12(GND57) J2.A13(GND56) J2.A14(GND55) J2.A15(GND54) J2.A16(GND53) J2.A17(GND52) J2.A18(GND51) J2.A19(GND50) J2.A20(GND49) J2.A21(GND48) J2.A22(GND47) J2.A23(GND46) J2.A24(GND45) J2.A25(GND44) J2.A26(GND43) J2.A27(GND42) J2.A28(GND41) J2.A29(GND40) J2.A30(GND39) J2.A31(GND38) J2.A32(GND37) J2.A33(GND36) J2.A34(GND35) J2.A35(GND34) J2.A36(GND33) J2.A37(GND32) J2.A38(GND31) J2.A39(GND30) J2.A40(GND29) J2.A41(GND28) J2.A42(GND27) J2.A43(GND26) J2.A44(GND25) J2.A45(GND24) J2.A46(GND23) J2.A47(GND22) J2.A48(GND21) J2.A49(GND20) J2.A50(GND19) J2.B3(GND18) J2.B5(GND16) J2.B6(GND15) J2.B8(GND14) J2.B10(GND13) J2.B12(GND12) J2.B14(GND11) J2.B16(GND10) J2.B18(GND9) J2.B20(GND8) J2.B22(GND7) J2.B24(GND6) J2.B26(GND5) J2.B28(GND4) J2.B30(GND3) J2.B32(GND2) J2.B34(GND1) J2.B36(GND0) J2.B38(GND130) J2.B40(GND129) J2.B42(GND128) J2.B44(GND127) J2.B46(GND126) J2.B48(GND125) J2.B49(GND124) J2.B50(GND123) J2.C3(GND122) J2.C5(GND120) J2.C6(GND143) J2.C8(GND142) J2.C10(GND261) J2.C12(GND141) J2.C14(GND140) J2.C16(GND139) J2.C18(GND138) J2.C20(GND137) J2.C22(GND136) J2.C24(GND135) J2.C26(GND134) J2.C28(GND133) J2.C30(GND132) J2.C32(GND131) J2.C34(GND260) J2.C36(GND259) J2.C38(GND258) J2.C40(GND257) J2.C42(GND256) J2.C44(GND255) J2.C46(GND254) J2.C48(GND253) J2.C49(GND252) J2.C50(GND251) J2.D3(GND250) J2.D4(GND249) J2.D6(GND247) J2.D7(GND246) J2.D9(GND222) J2.D11(GND221) J2.D13(GND220) J2.D15(GND219) J2.D17(GND218) J2.D19(GND217) J2.D21(GND216) J2.D23(GND215) J2.D25(GND214) J2.D27(GND213) J2.D29(GND212) J2.D31(GND211) J2.D33(GND210) J2.D35(GND209) J2.D37(GND208) J2.D39(GND207) J2.D41(GND206) J2.D43(GND205) J2.D45(GND204) J2.D47(GND203) J2.D49(GND232) J2.D50(GND231) J2.E3(GND245) J2.E4(GND244) J2.E6(GND242) J2.E7(GND241) J2.E9(GND202) J2.E11(GND201) J2.E13(GND200) J2.E15(GND199) J2.E17(GND198) J2.E19(GND197) J2.E21(GND196) J2.E23(GND80) J2.E25(GND79) J2.E27(GND78) J2.E29(GND77) J2.E31(GND76) J2.E33(GND75) J2.E35(GND74) J2.E37(GND73) J2.E39(GND72) J2.E41(GND71) J2.E43(GND70) J2.E45(GND69) J2.E47(GND195) J2.E49(GND230) J2.E50(GND229) J2.F3(GND240) J2.F5(GND238) J2.F6(GND237) J2.F8(GND194) J2.F10(GND119) J2.F12(GND118) J2.F14(GND117) J2.F16(GND116) J2.F18(GND115) J2.F20(GND114) J2.F22(GND113) J2.F24(GND112) J2.F26(GND111) J2.F28(GND110) J2.F30(GND109) J2.F32(GND108) J2.F34(GND107) J2.F36(GND106) J2.F38(GND105) J2.F40(GND104) J2.F42(GND103) J2.F44(GND102) J2.F46(GND101) J2.F48(GND228) J2.F49(GND227) J2.F50(GND226) J2.G3(GND236) J2.G5(GND234) J2.G6(GND233) J2.G8(GND100) J2.G10(GND99) J2.G12(GND98) J2.G14(GND97) J2.G16(GND96) J2.G18(GND95) J2.G20(GND94) J2.G22(GND93) J2.G24(GND92) J2.G26(GND91) J2.G28(GND90) J2.G30(GND89) J2.G32(GND88) J2.G34(GND87) J2.G36(GND86) J2.G38(GND85) J2.G40(GND84) J2.G42(GND83) J2.G44(GND82) J2.G46(GND81) J2.G48(GND225) J2.G49(GND224) J2.G50(GND223) J2.H1(GND193) J2.H2(GND192) J2.H3(GND191) J2.H4(GND190) J2.H5(GND189) J2.H6(GND188) J2.H7(GND187) J2.H8(GND186) J2.H9(GND185) J2.H10(GND184) J2.H11(GND183) J2.H12(GND182) J2.H13(GND181) J2.H14(GND180) J2.H15(GND179) J2.H16(GND178) J2.H17(GND177) J2.H18(GND176) J2.H19(GND175) J2.H20(GND174) J2.H21(GND173) J2.H22(GND172) J2.H23(GND171) J2.H24(GND170) J2.H25(GND169) J2.H26(GND168) J2.H27(GND167) J2.H28(GND166) J2.H29(GND165) J2.H30(GND164) J2.H31(GND163) J2.H32(GND162) J2.H33(GND161) J2.H34(GND160) J2.H35(GND159) J2.H36(GND158) J2.H37(GND157) J2.H38(GND156) J2.H39(GND155) J2.H40(GND154) J2.H41(GND153) J2.H42(GND152) J2.H43(GND151) J2.H44(GND150) J2.H45(GND149) J2.H46(GND148) J2.H47(GND147) J2.H48(GND146) J2.H49(GND145) J2.H50(GND144) J3.6(VSS) J3.10(GND) J3.11(Sh1) J3.12(Sh2) J3.13(Sh3) J17.1(CONFIG_3) J17.3(GND3) J17.9(GND9) J17.15(GND15) J17.21(CONFIG_0) J17.27(GND27) J17.33(Gen) J17.39(GND39) J17.45(GND45) J17.51(GND51) J17.57(GND57) J17.71(Gnd71) J17.73(Gnd73) J17.75(CONFIG_2) J18.7(GND_DRAIN) JA1.2(SHIELD1) JA1.3(SHIELD2) JA1.4(SHIELD3) JA1.5(SHIELD4) JA2.2(SHIELD1) JA2.3(SHIELD2) JA2.4(SHIELD3) JA2.5(SHIELD4) JA3.2(SHIELD1) JA3.3(SHIELD2) JA3.4(SHIELD3) JA3.5(SHIELD4) JA4.2(SHIELD1) JA4.3(SHIELD2) JA4.4(SHIELD3) JA4.5(SHIELD4) JA5.2(SHIELD1) JA5.3(SHIELD2) JA5.4(SHIELD3) JA5.5(SHIELD4) JA6.2(SHIELD1) JA6.3(SHIELD2) JA6.4(SHIELD3) JA6.5(SHIELD4) JA17.2(SHIELD1) JA17.3(SHIELD2) JA17.4(SHIELD3) JA17.5(SHIELD4) JU1.5(G1) JU1.6(G3) JU1.7(G2) R68.1 R69.1 R73.2 RAB3.2 RAB4.2 RAB7.2 RAB8.2 RAB11.2 RAB12.2 RAB15.2 RAB16.2 RAB19.2 RAB20.2 RAB23.2 RAB24.2 TAB1.1(PRI1) TAB1.2(PRI2) TAB1.5(NC) TAB2.1(PRI1) TAB2.2(PRI2) TAB2.5(NC) TAB3.1(PRI1) TAB3.2(PRI2) TAB3.5(NC) TAB4.1(PRI1) TAB4.2(PRI2) TAB4.5(NC) TAB5.1(PRI1) TAB5.2(PRI2) TAB5.5(NC) TAB6.1(PRI1) TAB6.2(PRI2) TAB6.5(NC) U13.5(GND) U15.33(CTR_GND) U17.3(GND) U18.9(GND1) U18.10(GND2) UG1.10(GND10) UG1.12(GND12) UG1.13(GND13) UG1.24(GND24) X1.2(GND) XS2.3(GND) Y7.3(GND) ; also on sheet 2 3 4 5 6 7 8 9 10 11 12 25 27 28
VCC_5V: C290.1 J1.B1(VCC1A) J1.B2(VCC1B) J1.C1(VCC1C) J1.C2(VCC1D) J1.D1(VCC2A) J1.D2(VCC2B) J1.E1(VCC2C) J1.E2(VCC2D) J1.F1(VCC3A) J1.F2(VCC3B) J1.G1(VCC3C) J1.G2(VCC3D) J2.F1(VCC3D) J2.G1(VCC3B) J2.G2(VCC3C) U15.21(VBAT) U17.7(IN) ; also on sheet 6 28
VCCO_89: J2.B2(VCC1A) J2.C1(VCC1B) J2.C2(VCC1C) ; also on sheet 5
VCCO_501: J2.E1(VCC2C) J2.E2(VCC2D) J2.F2(VCC3A) ; also on sheet 5
VCCO_502: J2.B1(VCC1D) J2.D1(VCC2A) J2.D2(VCC2B) ; also on sheet 5
BANK128_MGT_CLK1_N: J2.E40(IO_50_N) ; also on sheet 25
BANK128_MGT_CLK1_P: J2.D40(IO_50_P) ; also on sheet 25
BANK128_MGT_RX0_N: J2.C39(IO_49_N) ; also on sheet 25
BANK128_MGT_RX0_P: J2.B39(IO_49_P) ; also on sheet 25
BANK128_MGT_RX1_N: J2.G37(IO_48_N) ; also on sheet 25
BANK128_MGT_RX1_P: J2.F37(IO_48_P) ; also on sheet 25
BANK128_MGT_RX2_N: J2.E38(IO_47_N) ; also on sheet 25
BANK128_MGT_RX2_P: J2.D38(IO_47_P) ; also on sheet 25
BANK128_MGT_RX3_N: J2.C37(IO_46_N) ; also on sheet 25
BANK128_MGT_RX3_P: J2.B37(IO_46_P) ; also on sheet 25
BANK128_MGT_TX0_N: J2.G41(IO_54_N) ; also on sheet 25
BANK128_MGT_TX0_P: J2.F41(IO_54_P) ; also on sheet 25
BANK128_MGT_TX1_N: J2.E42(IO_53_N) ; also on sheet 25
BANK128_MGT_TX1_P: J2.D42(IO_53_P) ; also on sheet 25
BANK128_MGT_TX2_N: J2.G39(IO_51_N) ; also on sheet 25
BANK128_MGT_TX2_P: J2.F39(IO_51_P) ; also on sheet 25
BANK128_MGT_TX3_N: J2.C41(IO_52_N) ; also on sheet 25
BANK128_MGT_TX3_P: J2.B41(IO_52_P) ; also on sheet 25
BANK129_MGT_RX0_N: J2.C31(IO_37_N) ; also on sheet 3
BANK129_MGT_RX0_P: J2.B31(IO_37_P) ; also on sheet 3
BANK129_MGT_TX0_N: J2.E34(IO_41_N) ; also on sheet 3
BANK129_MGT_TX0_P: J2.D34(IO_41_P) ; also on sheet 3
BANK501_PS_MIO30: J2.D8(IO_2_P) ; also on sheet 28
BANK501_PS_MIO31: J2.C15(IO_13_N) ; also on sheet 28
BANK501_PS_MIO32: J2.D10(IO_5_P) ; also on sheet 28
BANK501_PS_MIO33: J2.B15(IO_13_P) ; also on sheet 28
BANK501_PS_MIO34: J2.G7(IO_3_N) ; also on sheet 28
BANK501_PS_MIO35: J2.C11(IO_7_N) ; also on sheet 28
BANK501_PS_MIO38: J2.G9(IO_6_N) ; also on sheet 28
BANK501_PS_MIO39: J2.E10(IO_5_N) ; also on sheet 28
BANK501_PS_MIO40: J2.B11(IO_7_P) ; also on sheet 28
BANK501_PS_MIO41: J2.F9(IO_6_P) ; also on sheet 28
BANK505_MGT_CLK0_N: J2.G33(IO_42_N) U13.9(4Z)
BANK505_MGT_CLK0_P: J2.F33(IO_42_P) U13.10(4Y)
BANK505_MGT_CLK2_N: J2.E36(IO_44_N) Y7.5(OUT-)
BANK505_MGT_CLK2_P: J2.D36(IO_44_P) Y7.4(OUT+)
BANK505_MGT_RX0_N: C72.2 J2.E48(IO_62_N)
BANK505_MGT_RX0_P: C73.2 J2.D48(IO_62_P)
BANK505_MGT_RX1_N: C68.2 J2.C47(IO_61_N)
BANK505_MGT_RX1_P: C69.2 J2.B47(IO_61_P)
BANK505_MGT_RX2_N: C92.2 J2.G45(IO_60_N)
BANK505_MGT_RX2_P: C95.2 J2.F45(IO_60_P)
BANK505_MGT_TX0_N: C74.2 J2.C45(IO_58_N)
BANK505_MGT_TX0_P: C75.2 J2.B45(IO_58_P)
BANK505_MGT_TX1_N: C70.2 J2.E44(IO_56_N)
BANK505_MGT_TX1_P: C71.2 J2.D44(IO_56_P)
BANK505_MGT_TX2_N: C97.2 J2.G43(IO_57_N)
BANK505_MGT_TX2_P: C96.2 J2.F43(IO_57_P)
CLK_100M_N: U13.7(NC) XS2.5(CLKN)
CLK_100M_P: U13.6(A) XS2.4(CLKP)
CLKIN0_N: J2.G4(REFCLK_N) ; also on sheet 7
CLKIN0_P: J2.F4(REFCLK_P) ; also on sheet 7
GPS_USB_DN: JU1.2(D-) UG1.5(USB_DM)
GPS_USB_DP: JU1.3(D+) UG1.6(USB_DP)
JTAG_TCK: J2.E28(IO_32_N) ; also on sheet 27
JTAG_TDI: J2.F23(IO_27_P) ; also on sheet 27
JTAG_TDO: J2.B25(IO_28_P) ; also on sheet 27
JTAG_TMS: J2.D26(IO_29_P) ; also on sheet 27
LEDG0: J1.C13(DFFIO10-) ; also on sheet 28
LEDG1: J1.G7(DFFIO3-) ; also on sheet 28
LEDG2: J1.G13(DFFIO12-) ; also on sheet 28
LEDG3: J1.F7(DFFIO3+) ; also on sheet 28
M2_DEV_CLKN: C76.2 U13.15(1Z)
M2_DEV_CLKP: C77.2 U13.16(1Y)
M2_NVME_DET: J17.69(CONFIG_1) R64.2
M2_PERST: J2.F7(IO_3_P) J17.50(PERST#) R63.2
NVME_ACT: D8.2(CATHODE) J17.10(DAS/DSS)
PHY_MDC: J2.D24(IO_26_P) ; also on sheet 2
PHY_MDIO: J2.E24(IO_26_N) ; also on sheet 2
PHY_RX_CLK: J2.G21(IO_24_N) ; also on sheet 2
PHY_RX_CTRL: J2.F21(IO_24_P) ; also on sheet 2
PHY_RXD0: J2.E20(IO_20_N) ; also on sheet 2
PHY_RXD1: J2.D22(IO_23_P) ; also on sheet 2
PHY_RXD2: J2.B23(IO_25_P) ; also on sheet 2
PHY_RXD3: J2.E22(IO_23_N) ; also on sheet 2
PHY_TX_CLK: J2.F19(IO_21_P) ; also on sheet 2
PHY_TX_CTRL: J2.C21(IO_22_N) ; also on sheet 2
PHY_TXD0: J2.G19(IO_21_N) ; also on sheet 2
PHY_TXD1: J2.C17(IO_16_N) ; also on sheet 2
PHY_TXD2: J2.B17(IO_16_P) ; also on sheet 2
PHY_TXD3: J2.C23(IO_25_N) ; also on sheet 2
PPS_1S_GPS: J1.B9(DFFIO4+) UG1.3(TIMEPLUSE)
PS_DONE: J2.C27(IO_31_N) ; also on sheet 7
PS_ERR_STAT: J2.C25(IO_28_N) ; also on sheet 7
PS_ERROR: J2.G23(IO_27_N) ; also on sheet 7
PS_MODE0: J2.G25(IO_30_N) ; also on sheet 7
PS_MODE1: J2.E26(IO_29_N) ; also on sheet 7
PS_MODE2: J2.F25(IO_30_P) ; also on sheet 7
PS_MODE3: J2.D28(IO_32_P) ; also on sheet 7
PS_POR: J2.G11(IO_9_N) ; also on sheet 2
RX_00_N: J1.C46(ADC1-) ; also on sheet 11
RX_00_P: J1.B46(ADC1+) ; also on sheet 11
RX_01_N: J1.G46(ADC2-) ; also on sheet 11
RX_01_P: J1.F46(ADC2+) ; also on sheet 11
RX_02_N: J1.C42(ADC3-) ; also on sheet 10
RX_02_P: J1.B42(ADC3+) ; also on sheet 10
RX_03_N: J1.G42(ADC4-) ; also on sheet 10
RX_03_P: J1.F42(ADC4+) ; also on sheet 10
RX_04_N: J1.C38(ADC5-) ; also on sheet 9
RX_04_P: J1.B38(ADC5+) ; also on sheet 9
RX_05_N: J1.G38(ADC6-) ; also on sheet 9
RX_05_P: J1.F38(ADC6+) ; also on sheet 9
RX_06_N: J1.C34(ADC7-) ; also on sheet 8
RX_06_P: J1.B34(ADC7+) ; also on sheet 8
RX_07_N: J1.G34(ADC8-) ; also on sheet 8
RX_07_P: J1.F34(ADC8+) ; also on sheet 8
RXD_GPS: J2.C7(IO_1_N) RG3.1
SDIO_CLK: J2.G13(IO_12_N) J3.5(CLK)
SDIO_CMD: J2.C13(IO_10_N) J3.3(CMD)
SDIO_DAT0: J2.D12(IO_8_P) J3.7(DAT0)
SDIO_DAT1: J2.E14(IO_11_N) J3.8(DAT1)
SDIO_DAT2: J2.F13(IO_12_P) J3.1(DAT2)
SDIO_DAT3: J2.D14(IO_11_P) J3.2(DAT3) R2.2
SDIO_DETECT: J2.E12(IO_8_N) J3.9(CD) R1.2
SYS_CLK_OUT_N: J2.C4(CLKOUT_N) ; also on sheet 7
SYS_CLK_OUT_P: J2.B4(CLKOUT_P) ; also on sheet 7
SYS_RESET#: J2.B27(IO_31_P) ; also on sheet 7
SYSREF_IN_N: J2.E5(SYSREF_N) ; also on sheet 7
SYSREF_IN_P: J2.D5(SYSREF_P) ; also on sheet 7
TRIG_IN: J1.C7(DFFIO1-) ; also on sheet 7
TRIG_OUT: J1.B7(DFFIO1+) ; also on sheet 7
TX_00_N: J1.C30(DAC1-) LAB2.2 LAB3.2
TX_00_P: J1.B30(DAC1+) LAB3.1 LAB4.2
TX_01_N: J1.G30(DAC2-) LAB7.2 LAB8.2
TX_01_P: J1.F30(DAC2+) LAB8.1 LAB9.2
TX_02_N: J1.C26(DAC3-) LAB12.2 LAB13.2
TX_02_P: J1.B26(DAC3+) LAB13.1 LAB14.2
TX_03_N: J1.G26(DAC4-) LAB17.2 LAB18.2
TX_03_P: J1.F26(DAC4+) LAB18.1 LAB19.2
TX_04_N: J1.C22(DAC5-) LAB22.2 LAB23.2
TX_04_P: J1.B22(DAC5+) LAB23.1 LAB24.2
TX_05_N: J1.G22(DAC6-) LAB27.2 LAB28.2
TX_05_P: J1.F22(DAC6+) LAB28.1 LAB29.2
TX_06_N: J1.C18(DAC7-) ; also on sheet 12
TX_06_P: J1.B18(DAC7+) ; also on sheet 12
TX_07_N: J1.G18(DAC8-) ; also on sheet 12
TX_07_P: J1.F18(DAC8+) ; also on sheet 12
TXD_GPS: J1.B13(DFFIO10+) J2.B9(IO_4_P) RG2.1
UART0_RX: J2.B13(IO_10_P) ; also on sheet 27
UART0_TX: J2.F11(IO_9_P) ; also on sheet 27
USB_5V: C93.1 C94.1 D9.2 D10.2 FB12.1 R67.1 U17.6(OUT2) U17.8(OUT1)
USB_CLK: R70.1 U15.26(EFCLK)
USB_CLKOUT: J2.C19(IO_19_N) U15.1(CLKOUT)
USB_CPEN: U15.17(CPEN33) U17.1(EN)
USB_DATA0: J2.D16(IO_14_P) U15.3(DATA0)
USB_DATA1: J2.B19(IO_19_P) U15.4(DATA1)
USB_DATA2: J2.D18(IO_17_P) U15.5(DATA2)
USB_DATA3: J2.E16(IO_14_N) U15.6(DATA3)
USB_DATA4: J2.G15(IO_15_N) U15.7(DATA4)
USB_DATA5: J2.B21(IO_22_P) U15.9(DATA5)
USB_DATA6: J2.G17(IO_18_N) U15.10(DATA6)
USB_DATA7: J2.F17(IO_18_P) U15.13(DATA7)
USB_DIR: J2.D20(IO_20_P) U15.31(DIR)
USB_DM: D9.3 J18.2(D-) U15.19(DM)
USB_DP: D10.3 J18.3(D+) U15.18(DP)
USB_ID: R69.2 U15.23(ID)
USB_NXT: J2.E18(IO_17_N) U15.2(NXT)
USB_RESET#: J2.E8(IO_2_N) R66.2 U15.27(RESETB)
USB_RX_N: C92.1 J18.5(StdA_SSTX-) U18.1(IN1) U18.8(OUT1)
USB_RX_P: C95.1 J18.6(StdA_SSTX+) U18.2(IN2) U18.7(OUT2)
USB_STP: J2.F15(IO_15_P) U15.29(STP)
USB_TX_N: C88.1 C97.1 U18.3(IN3) U18.6(OUT3)
USB_TX_P: C89.1 C96.1 U18.4(IN4) U18.5(OUT4)
USER_IO0: J1.C11(DFFIO7-) ; also on sheet 28
USER_IO1: J1.F9(DFFIO6+) ; also on sheet 28
USER_IO2: J1.G9(DFFIO6-) ; also on sheet 28
USER_IO3: J1.D14(DFFIO11+) ; also on sheet 28
USER_IO4: J1.E14(DFFIO11-) ; also on sheet 28
USER_IO5: J1.F11(DFFIO9+) ; also on sheet 28
USER_IO6: J1.G11(DFFIO9-) ; also on sheet 28
USER_IO7: J1.F13(DFFIO12+) ; also on sheet 28
USER_IOB0: J1.C9(DFFIO4-) ; also on sheet 28
USER_IOB1: J1.D8(DFFIO2+) ; also on sheet 28
USER_IOB2: J1.E8(DFFIO2-) ; also on sheet 28
USER_IOB3: J1.D10(DFFIO5+) ; also on sheet 28
USER_IOB4: J1.E10(DFFIO5-) ; also on sheet 28
USER_IOB5: J1.D12(DFFIO8+) ; also on sheet 28
USER_IOB6: J1.E12(DFFIO8-) ; also on sheet 28
USER_IOB7: J1.B11(DFFIO7+) ; also on sheet 28
N21034969: RG1.1 UG1.9(VCC_RF)
N21034983: JA17.1(CENTER) LG1.2 UG1.11(RF_IN)
N21034987: CG1.1 LG1.1 RG1.2
N22362940: R70.2 X1.3(OUT)
N22363073: C87.2 FB13.2 J18.4(GND)
N22363075: C91.1 FB14.2 J18.10(Shield1) J18.11(Shield2)
N22363103: C87.1 FB12.2 J18.1(VBUS)
N22363153: D11.2(CATHODE) U17.2(FLG)
N22692224: LAB2.1 TAB1.4(SE)
N22692289: CAB4.1 TAB1.3(PR_D)
N22692291: CAB4.2 RAB2.1 RAB3.1
N22692307: CAB6.1 RAB2.2 RAB4.1
N22692313: CAB6.2 JA1.1(CENTER)
N22692315: LAB4.1 TAB1.6(SE_D)
N22692505: LAB7.1 TAB2.4(SE)
N22692570: CAB10.1 TAB2.3(PR_D)
N22692582: CAB10.2 RAB6.1 RAB7.1
N22692588: CAB12.1 RAB6.2 RAB8.1
N22692594: CAB12.2 JA2.1(CENTER)
N22692596: LAB9.1 TAB2.6(SE_D)
N22693543: LAB12.1 TAB3.4(SE)
N22693600: CAB16.1 TAB3.3(PR_D)
N22693620: CAB16.2 RAB10.1 RAB11.1
N22693626: CAB18.1 RAB10.2 RAB12.1
N22693632: CAB18.2 JA3.1(CENTER)
N22693634: LAB14.1 TAB3.6(SE_D)
N22693824: LAB17.1 TAB4.4(SE)
N22693889: CAB22.1 TAB4.3(PR_D)
N22693901: CAB22.2 RAB14.1 RAB15.1
N22693907: CAB24.1 RAB14.2 RAB16.1
N22693913: CAB24.2 JA4.1(CENTER)
N22693915: LAB19.1 TAB4.6(SE_D)
N22694836: LAB22.1 TAB5.4(SE)
N22694901: CAB28.1 TAB5.3(PR_D)
N22694903: CAB28.2 RAB18.1 RAB19.1
N22694919: CAB30.1 RAB18.2 RAB20.1
N22694925: CAB30.2 JA5.1(CENTER)
N22694927: LAB24.1 TAB5.6(SE_D)
N22695117: LAB27.1 TAB6.4(SE)
N22695182: CAB34.1 TAB6.3(PR_D)
N22695184: CAB34.2 RAB22.1 RAB23.1
N22695200: CAB36.1 RAB22.2 RAB24.1
N22695206: CAB36.2 JA6.1(CENTER)
N22695208: LAB29.1 TAB6.6(SE_D)
N23191319: RG2.2 UG1.20(TXD_MISO)
N23191322: FBA1.1 UG1.22(V_BCKP)
N23191323: RG3.2 UG1.21(RXD_MOSI)
N23191324: FBA2.1 UG1.23(VCC)
N23203220: C71.1 J17.37(PETp1)
N23203222: C77.1 J17.55(REFCLKP)
N23203224: D8.1(ANODE) R62.2
N23203226: C70.1 J17.35(PETn1)
N23203229: C68.1 J17.29(PERn1)
N23203231: C76.1 J17.53(REFCLKN)
N23203232: C73.1 J17.43(SATA-B-/PERp0)
N23203233: C75.1 J17.49(SATA-A+/PETp0)
N23203234: C74.1 J17.47(SATA-A-/PETn0)
N23203235: C72.1 J17.41(SATA-B+/PERn0)
N23203242: C69.1 J17.31(PERp1)
N23203408: C88.2 J18.8(StdA_SSRX-)
N23203414: C89.2 J18.9(StdA_SSRX+)
N23203415: R208.1 Y7.1(OE)
N23203419: R67.2 U15.22(VBUS)
N23203420: R73.1 U17.4(NC)
N23203425: D11.1(ANODE) R72.1
N23203426: C90.1 U15.20(VDD33_P)
N23203427: R68.2 U15.24(RBIAS_23)

Not connected (* = marked no-connect by the designer): J1 D33(VCM7)* D37(VCM5)* D41(VCM3)* D45(VCM1)* E35(VCM8)* E39(VCM6)* E43(VCM4)* E47(VCM2)*; J2 B7(IO_1_P)* B29(IO_34_P)* B33(IO_40_P)* B35(IO_43_P)* B43(IO_55_P)* C9(IO_4_N)* C29(IO_34_N)* C33(IO_40_N)* C35(IO_43_N)* C43(IO_55_N)* D30(IO_35_P)* D32(IO_38_P)* D46(IO_59_P)* E30(IO_35_N)* E32(IO_38_N)* E46(IO_59_N)* F27(IO_33_P)* F29(IO_36_P)* F31(IO_39_P)* F35(IO_45_P)* F47(IO_63_P)* G27(IO_33_N)* G29(IO_36_N)* G31(IO_39_N)* G35(IO_45_N)* G47(IO_63_N)*; J3 14(GND1) 15(GND2); J17 5(PERn3) 6(NC1) 7(PERp3) 8(NC2) 11(PETn3) 13(PETp3) 17(PERn2) 19(PERp2) 20(NC3) 22(NC4) 23(PETn2) 24(NC5) 25(PETp2) 26(NC6) 28(NC7) 30(NC8) 32(NC9) 34(NC10) 36(NC11) 38(DEVSLP) 40(NC12) 42(NC13) 44(NC14) 46(NC15) 48(NC16) 52(CLKREQ#) 54(PEWAKE#) 56(MFG1) 58(MFG2) 67(NC17) 68(SUSCLK) 76(PAD1) 77(PAD2) 78(SH1) 79(SH2); JU1 1(VB)* 4(ID)*; U13 11(3Z) 12(3Y) 13(2Z) 14(2Y); U15 12(NC) 15(SPK_L) 16(SPK_R) 25(XO); U17 5(NC2); UG1 1(SAFEBOOT) 2(D_DEL) 4(EXTINT) 8(RESET_N) 14(LNA_EN) 15(RESERV15) 16(RESERV16) 17(RESERV17) 18(SDA_SCS) 19(SCL_SCLK); X1 1(NC)*; XS2 2(NC)*; Y7 2(NC)*

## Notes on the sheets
sheet 13
- V3BEST
- RFSOM_EVM_REV12
- 09 RF_TX03
sheet 14
- V3BEST
- RFSOM_EVM_REV12
- 08 RF_TX02
sheet 15
- V3BEST
- RFSOM_EVM_REV12
- 07 RF_TX01
sheet 16
- TOP_Layer
- BOT_Layer
- V3BEST
- RFSOM_EVM_REV12
- 06 CORE_CONNECTOR03
sheet 17
- BANK129_MGT_RX3_N
- BANK129_MGT_RX3_P
- BANK501_PS_MIO26
- BANK501_PS_MIO28
- BANK129_MGT_RX2_P
- BANK501_PS_MIO30
- BANK129_MGT_RX2_N
- BANK501_PS_MIO36
- BANK129_MGT_RX1_P
- BANK501_PS_MIO37
- BANK129_MGT_RX1_N
- BANK501_PS_MIO34
- BANK129_MGT_RX0_P
- BANK501_PS_MIO29
- BANK129_MGT_RX0_N
- BANK129_MGT_TX3_P
- BANK501_PS_MIO27
- BANK501_PS_MIO32
- BANK129_MGT_TX3_N
- BANK501_PS_MIO39
- BANK129_MGT_TX2_P
- BANK501_PS_MIO41
- BANK129_MGT_TX2_N
- BANK501_PS_MIO38
- BANK129_MGT_TX1_P
- BANK501_PS_MIO40
- BANK129_MGT_TX0_P
- BANK129_MGT_TX1_N
- BANK501_PS_MIO35
- BANK501_PS_MIO46
- BANK129_MGT_TX0_N
- BANK501_PS_MIO45
- BANK505_MGT_CLK0_P
- BANK501_PS_MIO43
- BANK505_MGT_CLK0_N
- BANK501_PS_MIO44
- BANK505_MGT_CLK1_P
- BANK501_PS_MIO42
- BANK505_MGT_CLK1_N
- BANK501_PS_MIO50
- BANK505_MGT_CLK2_N
- BANK505_MGT_CLK2_P
- BANK501_PS_MIO47
- BANK501_PS_MIO49
- BANK505_MGT_CLK3_P
- BANK501_PS_MIO48
- BANK505_MGT_CLK3_N
- BANK501_PS_MIO51
- BANK501_PS_MIO33
- BANK501_PS_MIO31
- BANK128_MGT_RX3_N
- BANK128_MGT_RX3_P
- BANK502_PS_MIO56
- BANK502_PS_MIO59
- BANK128_MGT_RX2_P
- BANK502_PS_MIO58
- BANK128_MGT_RX2_N
- BANK502_PS_MIO60
- BANK128_MGT_RX1_P
- BANK502_PS_MIO67
- BANK128_MGT_RX1_N
- BANK502_PS_MIO66
- BANK128_MGT_RX0_P
- BANK502_PS_MIO54
- BANK128_MGT_CLK1_P
- BANK128_MGT_RX0_N
- BANK502_PS_MIO55
- BANK502_PS_MIO63
- BANK128_MGT_CLK1_N
- BANK502_PS_MIO62
- BANK128_MGT_TX2_P
- BANK128_MGT_TX2_N
- BANK128_MGT_TX3_P
- BANK502_PS_MIO57
- BANK128_MGT_TX1_P
- BANK128_MGT_TX3_N
- BANK502_PS_MIO52
- BANK502_PS_MIO53
- BANK128_MGT_TX1_N
- BANK502_PS_MIO71
- BANK128_MGT_TX0_P
- BANK502_PS_MIO64
- BANK128_MGT_TX0_N
- BANK502_PS_MIO65
- BANK505_MGT_TX3_P
- BANK502_PS_MIO61
- BANK505_MGT_TX3_N
- BANK502_PS_MIO69
- BANK505_MGT_TX1_P
- BANK505_MGT_TX2_P
- BANK502_PS_MIO72
- BANK502_PS_MIO74
- BANK505_MGT_TX2_P
- BANK502_PS_MIO75
- BANK505_MGT_TX2_N
- BANK502_PS_MIO70
- BANK505_MGT_TX0_P
- BANK502_PS_MIO73
- BANK505_MGT_TX0_N
- BANK502_PS_MIO68
- BANK505_MGT_RX3_N
- BANK505_MGT_RX3_P
- BANK502_PS_MIO76
- BANK502_PS_MIO77
- BANK505_MGT_RX2_P
- JTAG_TDI
- BANK505_MGT_RX2_N
- PS_ERROR
- BANK505_MGT_RX1_P
- JTAG_TDO
- BANK505_MGT_RX1_N
- PS_ERR_STAT
- BANK505_MGT_RX0_P
- JTAG_TMS
- BANK129_MGT_CLK1_P
- BANK505_MGT_RX0_N
- PS_MODE1
- PS_MODE2
- BANK129_MGT_CLK1_N
- PS_MODE0
- SYS_RESET#
- PS_DONE
- PS_MODE3
- JTAG_TCK
- CLKIN0_P
- CLKIN0_N
- V3BEST
- SYS_CLK_OUT_N
- SYS_CLK_OUT_P
- RFSOM_EVM_REV12
- SYSREF_IN_P
- SYSREF_IN_N
- 05 CORE_CONNECTOR02
sheet 18
- V3BEST
- RFSOM_EVM_REV12
- 04 CORE_CONNECTOR01
sheet 19
- BANK89_IO_L1P
- BANK89_IO_L1N
- BANK89_IO_L2P
- BANK89_IO_L2N
- BANK89_IO_L12P
- BANK89_IO_L12N
- BANK89_IO_L3P
- BANK89_IO_L3N
- BANK89_IO_GC_L5N
- BANK89_IO_GC_L5P
- BANK89_IO_GC_L8P
- BANK89_IO_GC_L8N
- BANK89_IO_GC_L7P
- BANK89_IO_GC_L7N
- BANK89_IO_GC_L6N
- BANK89_IO_GC_L6P
- BANK89_IO_L10P
- BANK89_IO_L10N
- BANK89_IO_L4P
- BANK89_IO_L4N
- BANK89_IO_L9P
- BANK89_IO_L11P
- BANK89_IO_L9N
- BANK89_IO_L11N
- VM01_00
- VM23_00
- VM23_01
- VM01_01
- VM23_02
- VM01_02
- VM23_03
- VM01_03
- V3BEST
- RFSOM_EVM_REV112
- 03 COER_CONNECTOR00
sheet 20
- 90 ohm impedance for USB 2.0
- 100 ohm for USB 3.0 TX+/- RX+/-
- current limit set to 230/19=1.2A
- V3BEST
- RFSOM_EVM_REV12
- 23 USB3.0
sheet 21
- NVME_Singal
- PIN4
- CONFIG1:NC=PCIE;GND=SATA
- V3BEST
- RFSOM_EVM_REV12
- 22 NVME
sheet 22
- 删掉时钟BUFFER  U11
- V3BEST
- RFSOM_EVM_REV12
- 00 PCB DESIGNER
sheet 23
- V3BEST
- RFSOM_EVM_REV12
- 15 FLASH
sheet 24
- V3BEST
- RFSOM_EVM_REV12
- 21 GPS
